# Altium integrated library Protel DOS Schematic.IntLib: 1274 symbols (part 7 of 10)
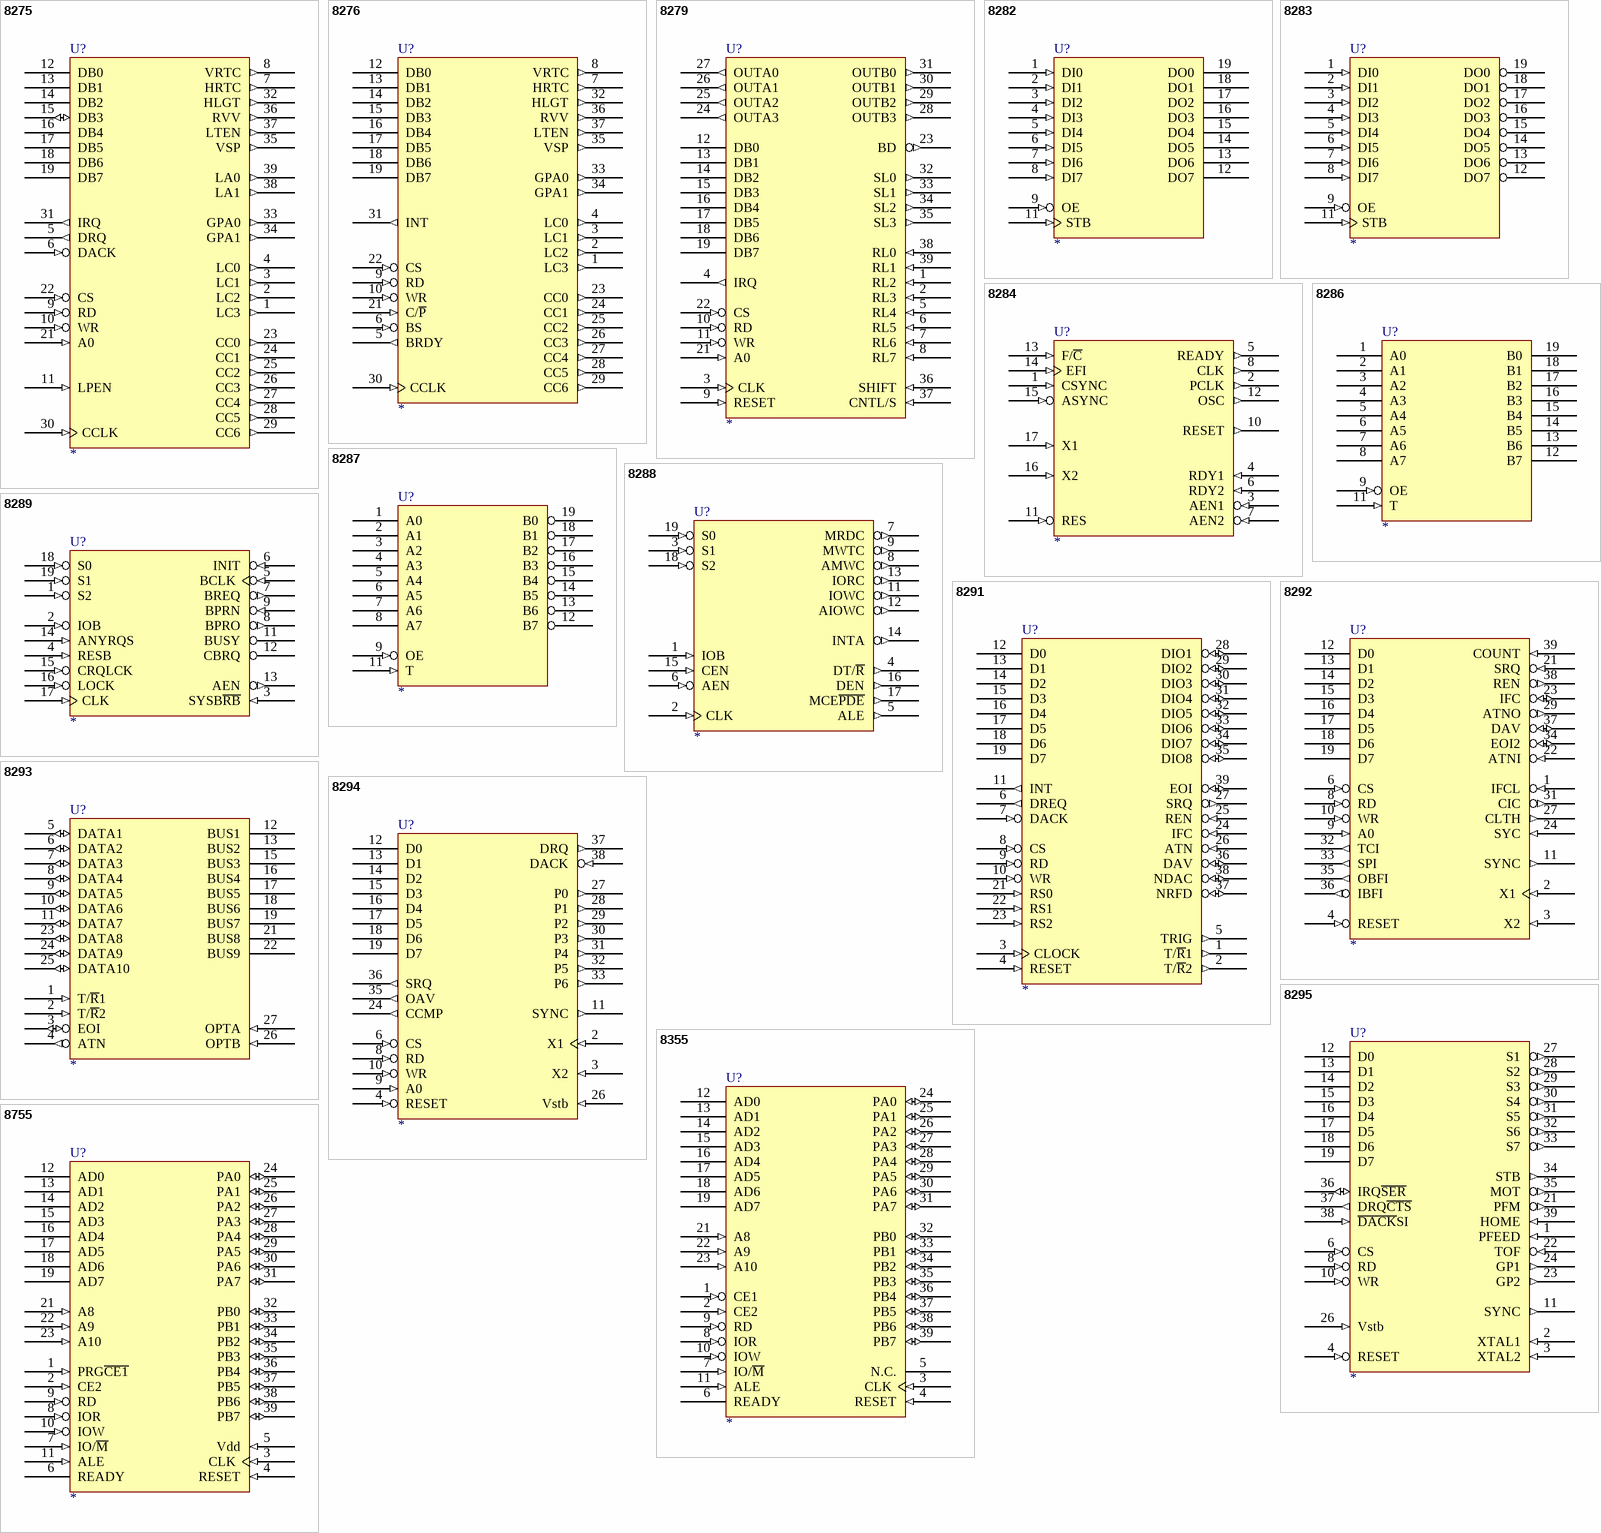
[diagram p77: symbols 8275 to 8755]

## 8293
designator U?
footprint DIP-28
pins: 1 T/~{R}1 (in), 2 T/~{R}2 (in), 3 EOI (io), 4 ATN (out), 5 DATA1 (io), 6 DATA2 (io), 7 DATA3 (io), 8 DATA4 (io), 9 DATA5 (io), 10 DATA6 (io), 11 DATA7 (io), 12 BUS1 (hiz), 13 BUS2 (hiz), 14 GND (power) hidden to GND, 15 BUS3 (hiz), 16 BUS4 (hiz), 17 BUS5 (hiz), 18 BUS6 (hiz), 19 BUS7 (hiz), 20 GND (power) hidden to GND, 21 BUS8 (hiz), 22 BUS9 (hiz), 23 DATA8 (io), 24 DATA9 (io), 25 DATA10 (io), 26 OPTB (in), 27 OPTA (in), 28 VCC (power) hidden to VCC
2 alternate drawings of the same symbol

## 8294
designator U?
footprint DIP-40
pins: 2 X1 (in), 3 X2 (in), 4 RESET (in), 5 VCC (power) hidden to VCC, 6 CS (in), 7 GND (power) hidden to GND, 8 RD (in), 9 A0 (in), 10 WR (in), 11 SYNC (out), 12 D0 (hiz), 13 D1 (hiz), 14 D2 (hiz), 15 D3 (hiz), 16 D4 (hiz), 17 D5 (hiz), 18 D6 (hiz), 19 D7 (hiz), 20 GND (power) hidden to GND, 24 CCMP (out), 25 VCC (power) hidden to VCC, 26 Vstb (in), 27 P0 (out), 28 P1 (out), 29 P2 (out), 30 P3 (out), 31 P4 (out), 32 P5 (out), 33 P6 (out), 35 OAV (out), 36 SRQ (out), 37 DRQ (out), 38 DACK (in), 40 VCC (power) hidden to VCC
2 alternate drawings of the same symbol

## 8295
designator U?
footprint DIP-40
pins: 1 PFEED (in), 2 XTAL1 (in), 3 XTAL2 (in), 4 RESET (in), 5 VCC (power) hidden to VCC, 6 CS (in), 7 GND (power) hidden to GND, 8 RD (in), 9 VCC (power) hidden to VCC, 10 WR (in), 11 SYNC (out), 12 D0 (hiz), 13 D1 (hiz), 14 D2 (hiz), 15 D3 (hiz), 16 D4 (hiz), 17 D5 (hiz), 18 D6 (hiz), 19 D7 (hiz), 20 GND (power) hidden to GND, 21 PFM (out), 22 TOF (in), 23 GP2 (out), 24 GP1 (out), 25 VCC (power) hidden to VCC, 26 Vstb (in), 27 S1 (out), 28 S2 (out), 29 S3 (out), 30 S4 (out), 31 S5 (out), 32 S6 (out), 33 S7 (out), 34 STB (out), 35 MOT (out), 36 IRQ~{SER} (io), 37 DRQ~{CTS} (out), 38 ~{DACK}SI (in), 39 HOME (in), 40 VCC (power) hidden to VCC
2 alternate drawings of the same symbol

## 8355
designator U?
footprint DIP-40
pins: 1 CE1 (in), 2 CE2 (in), 3 CLK (in), 4 RESET (in), 5 N.C., 6 READY (hiz), 7 IO/~{M} (in), 8 IOR (in), 9 RD (in), 10 IOW (in), 11 ALE (in), 12 AD0 (hiz), 13 AD1 (hiz), 14 AD2 (hiz), 15 AD3 (hiz), 16 AD4 (hiz), 17 AD5 (hiz), 18 AD6 (hiz), 19 AD7 (hiz), 20 GND (power) hidden to GND, 21 A8 (in), 22 A9 (in), 23 A10 (in), 24 PA0 (io), 25 PA1 (io), 26 PA2 (io), 27 PA3 (io), 28 PA4 (io), 29 PA5 (io), 30 PA6 (io), 31 PA7 (io), 32 PB0 (io), 33 PB1 (io), 34 PB2 (io), 35 PB3 (io), 36 PB4 (io), 37 PB5 (io), 38 PB6 (io), 39 PB7 (io), 40 VCC (power) hidden to VCC
2 alternate drawings of the same symbol

## 8755
designator U?
footprint DIP-40
pins: 1 PRG~{CE1} (in), 2 CE2 (in), 3 CLK (in), 4 RESET (in), 5 Vdd (in), 6 READY (hiz), 7 IO/~{M} (in), 8 IOR (in), 9 RD (in), 10 IOW (in), 11 ALE (in), 12 AD0 (hiz), 13 AD1 (hiz), 14 AD2 (hiz), 15 AD3 (hiz), 16 AD4 (hiz), 17 AD5 (hiz), 18 AD6 (hiz), 19 AD7 (hiz), 20 GND (power) hidden to GND, 21 A8 (in), 22 A9 (in), 23 A10 (in), 24 PA0 (io), 25 PA1 (io), 26 PA2 (io), 27 PA3 (io), 28 PA4 (io), 29 PA5 (io), 30 PA6 (io), 31 PA7 (io), 32 PB0 (io), 33 PB1 (io), 34 PB2 (io), 35 PB3 (io), 36 PB4 (io), 37 PB5 (io), 38 PB6 (io), 39 PB7 (io), 40 VCC (power) hidden to VCC
2 alternate drawings of the same symbol

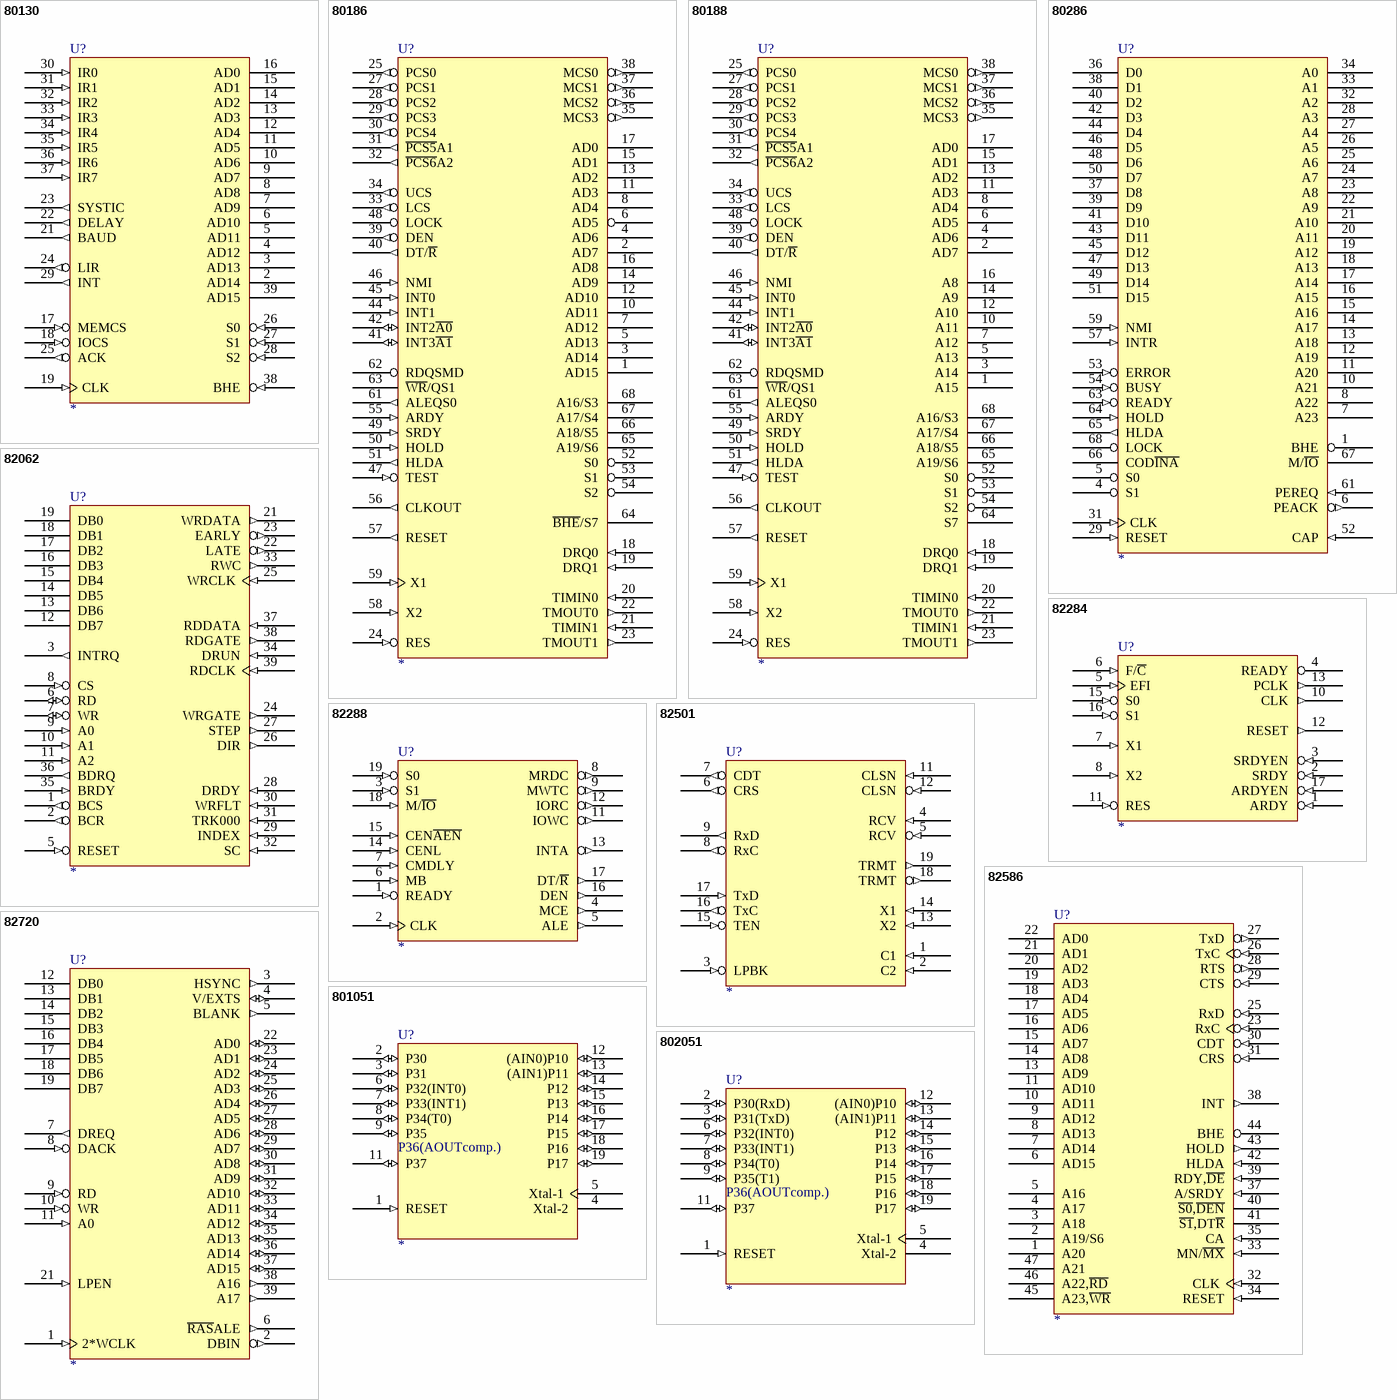
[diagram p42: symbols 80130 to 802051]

## 80130
designator U?
footprint DIP-40
pins: 1 GND (power) hidden to GND, 2 AD14 (hiz), 3 AD13 (hiz), 4 AD12 (hiz), 5 AD11 (hiz), 6 AD10 (hiz), 7 AD9 (hiz), 8 AD8 (hiz), 9 AD7 (hiz), 10 AD6 (hiz), 11 AD5 (hiz), 12 AD4 (hiz), 13 AD3 (hiz), 14 AD2 (hiz), 15 AD1 (hiz), 16 AD0 (hiz), 17 MEMCS (in), 18 IOCS (in), 19 CLK (in), 20 GND (power) hidden to GND, 21 BAUD (out), 22 DELAY (out), 23 SYSTIC (out), 24 LIR (out), 25 ACK (out), 26 S0 (in), 27 S1 (in), 28 S2 (in), 29 INT (out), 30 IR0 (in), 31 IR1 (in), 32 IR2 (in), 33 IR3 (in), 34 IR4 (in), 35 IR5 (in), 36 IR6 (in), 37 IR7 (in), 38 BHE (in), 39 AD15 (hiz), 40 VCC (power) hidden to VCC
2 alternate drawings of the same symbol

## 80186
designator U?
footprint JEDECA-68
pins: 1 AD15 (hiz), 2 AD7 (hiz), 3 AD14 (hiz), 4 AD6 (hiz), 5 AD13 (hiz), 6 AD5 (hiz), 7 AD12 (hiz), 8 AD4 (hiz), 9 VCC (power) hidden to VCC, 10 AD11 (hiz), 11 AD3 (hiz), 12 AD10 (hiz), 13 AD2 (hiz), 14 AD9 (hiz), 15 AD1 (hiz), 16 AD8 (hiz), 17 AD0 (hiz), 18 DRQ0 (in), 19 DRQ1 (in), 20 TIMIN0 (in), 21 TIMIN1 (in), 22 TMOUT0 (out), 23 TMOUT1 (out), 24 RES (in), 25 PCS0 (out), 26 GND (power) hidden to GND, 27 PCS1 (out), 28 PCS2 (out), 29 PCS3 (out), 30 PCS4 (out), 31 ~{PCS5}A1 (out), 32 ~{PCS6}A2 (out), 33 LCS (out), 34 UCS (out), 35 MCS3 (out), 36 MCS2 (out), 37 MCS1 (out), 38 MCS0 (out), 39 DEN (out), 40 DT/~{R} (out), 41 INT3~{A1} (io), 42 INT2~{A0} (io), 43 VCC (power) hidden to VCC, 44 INT1 (in), 45 INT0 (in), 46 NMI (in), 47 TEST (in), 48 LOCK (hiz), 49 SRDY (in), 50 HOLD (in), 51 HLDA (out), 52 S0 (hiz), 53 S1 (hiz), 54 S2 (hiz), 55 ARDY (in), 56 CLKOUT (out), 57 RESET (out), 58 X2 (in), 59 X1 (in), 60 GND (power) hidden to GND, 61 ALEQS0 (out), 62 RDQSMD (hiz), 63 ~{WR}/QS1 (hiz), 64 ~{BHE}/S7 (hiz), 65 A19/S6 (hiz), 66 A18/S5 (hiz), 67 A17/S4 (hiz), 68 A16/S3 (hiz)
2 alternate drawings of the same symbol

## 80188
designator U?
footprint JEDECA-68
pins: 1 A15 (hiz), 2 AD7 (hiz), 3 A14 (hiz), 4 AD6 (hiz), 5 A13 (hiz), 6 AD5 (hiz), 7 A12 (hiz), 8 AD4 (hiz), 9 VCC (power) hidden to VCC, 10 A11 (hiz), 11 AD3 (hiz), 12 A10 (hiz), 13 AD2 (hiz), 14 A9 (hiz), 15 AD1 (hiz), 16 A8 (hiz), 17 AD0 (hiz), 18 DRQ0 (in), 19 DRQ1 (in), 20 TIMIN0 (in), 21 TIMIN1 (in), 22 TMOUT0 (out), 23 TMOUT1 (out), 24 RES (in), 25 PCS0 (out), 26 GND (power) hidden to GND, 27 PCS1 (out), 28 PCS2 (out), 29 PCS3 (out), 30 PCS4 (out), 31 ~{PCS5}A1 (out), 32 ~{PCS6}A2 (out), 33 LCS (out), 34 UCS (out), 35 MCS3 (out), 36 MCS2 (out), 37 MCS1 (out), 38 MCS0 (out), 39 DEN (out), 40 DT/~{R} (out), 41 INT3~{A1} (io), 42 INT2~{A0} (io), 43 VCC (power) hidden to VCC, 44 INT1 (in), 45 INT0 (in), 46 NMI (in), 47 TEST (in), 48 LOCK (hiz), 49 SRDY (in), 50 HOLD (in), 51 HLDA (out), 52 S0 (hiz), 53 S1 (hiz), 54 S2 (hiz), 55 ARDY (in), 56 CLKOUT (out), 57 RESET (out), 58 X2 (in), 59 X1 (in), 60 GND (power) hidden to GND, 61 ALEQS0 (out), 62 RDQSMD (hiz), 63 ~{WR}/QS1 (hiz), 64 S7 (hiz), 65 A19/S6 (hiz), 66 A18/S5 (hiz), 67 A17/S4 (hiz), 68 A16/S3 (hiz)
2 alternate drawings of the same symbol

## 80286
designator U?
footprint JEDECA-68
pins: 1 BHE (hiz), 4 S1 (hiz), 5 S0 (hiz), 6 PEACK (out), 7 A23 (hiz), 8 A22 (hiz), 9 GND (power) hidden to GND, 10 A21 (hiz), 11 A20 (hiz), 12 A19 (hiz), 13 A18 (hiz), 14 A17 (hiz), 15 A16 (hiz), 16 A15 (hiz), 17 A14 (hiz), 18 A13 (hiz), 19 A12 (hiz), 20 A11 (hiz), 21 A10 (hiz), 22 A9 (hiz), 23 A8 (hiz), 24 A7 (hiz), 25 A6 (hiz), 26 A5 (hiz), 27 A4 (hiz), 28 A3 (hiz), 29 RESET (in), 30 VCC (power) hidden to VCC, 31 CLK (in), 32 A2 (hiz), 33 A1 (hiz), 34 A0 (hiz), 35 GND (power) hidden to GND, 36 D0 (hiz), 37 D8 (hiz), 38 D1 (hiz), 39 D9 (hiz), 40 D2 (hiz), 41 D10 (hiz), 42 D3 (hiz), 43 D11 (hiz), 44 D4 (hiz), 45 D12 (hiz), 46 D5 (hiz), 47 D13 (hiz), 48 D6 (hiz), 49 D14 (hiz), 50 D7 (hiz), 51 D15 (hiz), 52 CAP (in), 53 ERROR (in), 54 BUSY (in), 57 INTR (in), 59 NMI (in), 60 GND (power) hidden to GND, 61 PEREQ (in), 62 VCC (power) hidden to VCC, 63 READY (in), 64 HOLD (in), 65 HLDA (out), 66 COD~{INA} (hiz), 67 M/~{IO} (hiz), 68 LOCK (hiz)
2 alternate drawings of the same symbol

## 82062
designator U?
footprint DIP-40
pins: 1 BCS (out), 2 BCR (out), 3 INTRQ (out), 5 RESET (in), 6 RD (io), 7 WR (io), 8 CS (in), 9 A0 (in), 10 A1 (in), 11 A2 (in), 12 DB7 (hiz), 13 DB6 (hiz), 14 DB5 (hiz), 15 DB4 (hiz), 16 DB3 (hiz), 17 DB2 (hiz), 18 DB1 (hiz), 19 DB0 (hiz), 20 GND (power) hidden to GND, 21 WRDATA (out), 22 LATE (out), 23 EARLY (out), 24 WRGATE (out), 25 WRCLK (in), 26 DIR (out), 27 STEP (out), 28 DRDY (in), 29 INDEX (in), 30 WRFLT (in), 31 TRK000 (in), 32 SC (in), 33 RWC (out), 34 DRUN (in), 35 BRDY (in), 36 BDRQ (out), 37 RDDATA (in), 38 RDGATE (out), 39 RDCLK (in), 40 VCC (power) hidden to VCC
2 alternate drawings of the same symbol

## 82284
designator U?
footprint DIP-18
pins: 1 ARDY (in), 2 SRDY (in), 3 SRDYEN (in), 4 READY (oc), 5 EFI (in), 6 F/~{C} (in), 7 X1 (in), 8 X2 (in), 9 GND (power) hidden to GND, 10 CLK (out), 11 RES (in), 12 RESET (out), 13 PCLK (out), 15 S0 (in), 16 S1 (in), 17 ARDYEN (in), 18 VCC (power) hidden to VCC
2 alternate drawings of the same symbol

## 82288
designator U?
footprint DIP-20
pins: 1 READY (in), 2 CLK (in), 3 S1 (in), 4 MCE (out), 5 ALE (out), 6 MB (in), 7 CMDLY (in), 8 MRDC (out), 9 MWTC (out), 10 GND (power) hidden to GND, 11 IOWC (out), 12 IORC (out), 13 INTA (out), 14 CENL (in), 15 CEN~{AEN} (in), 16 DEN (out), 17 DT/~{R} (out), 18 M/~{IO} (in), 19 S0 (in), 20 VCC (power) hidden to VCC
2 alternate drawings of the same symbol

## 82501
designator U?
footprint DIP-20
pins: 1 C1 (in), 2 C2 (in), 3 LPBK (in), 4 RCV (in), 5 RCV (in), 6 CRS (out), 7 CDT (out), 8 RxC (out), 9 RxD (out), 10 GND (power) hidden to GND, 11 CLSN (in), 12 CLSN (in), 13 X2 (in), 14 X1 (in), 15 TEN (in), 16 TxC (out), 17 TxD (in), 18 TRMT (out), 19 TRMT (out), 20 VCC (power) hidden to VCC
2 alternate drawings of the same symbol

## 82586
designator U?
footprint DIP-48
pins: 1 A20 (hiz), 2 A19/S6 (hiz), 3 A18 (hiz), 4 A17 (hiz), 5 A16 (hiz), 6 AD15 (hiz), 7 AD14 (hiz), 8 AD13 (hiz), 9 AD12 (hiz), 10 AD11 (hiz), 11 AD10 (hiz), 12 GND (power) hidden to GND, 13 AD9 (hiz), 14 AD8 (hiz), 15 AD7 (hiz), 16 AD6 (hiz), 17 AD5 (hiz), 18 AD4 (hiz), 19 AD3 (hiz), 20 AD2 (hiz), 21 AD1 (hiz), 22 AD0 (hiz), 23 RxC (in), 24 GND (power) hidden to GND, 25 RxD (in), 26 TxC (in), 27 TxD (out), 28 RTS (out), 29 CTS (in), 30 CDT (in), 31 CRS (in), 32 CLK (in), 33 MN/~{MX} (in), 34 RESET (in), 35 CA (in), 36 VCC (power) hidden to VCC, 37 A/SRDY (in), 38 INT (out), 39 RDY,~{DE} (in), 40 ~{S0},~{DEN} (hiz), 41 ~{S1},DT~{R} (hiz), 42 HLDA (in), 43 HOLD (out), 44 BHE (hiz), 45 A23,~{WR} (hiz), 46 A22,~{RD} (hiz), 47 A21 (hiz), 48 VCC (power) hidden to VCC
2 alternate drawings of the same symbol

## 82720
designator U?
footprint DIP-40
pins: 1 2*WCLK (in), 2 VCC (power) hidden to VCC, 2 DBIN (out), 3 HSYNC (out), 4 V/EXTS (io), 5 BLANK (out), 6 ~{RAS}ALE (out), 7 DREQ (out), 8 DACK (in), 9 RD (in), 10 WR (in), 11 A0 (in), 12 DB0 (hiz), 13 DB1 (hiz), 14 DB2 (hiz), 15 DB3 (hiz), 16 DB4 (hiz), 17 DB5 (hiz), 18 DB6 (hiz), 19 DB7 (hiz), 20 GND (power) hidden to GND, 21 LPEN (in), 22 AD0 (io), 23 AD1 (io), 24 AD2 (io), 25 AD3 (io), 26 AD4 (io), 27 AD5 (io), 28 AD6 (io), 29 AD7 (io), 30 AD8 (io), 31 AD9 (io), 32 AD10 (io), 33 AD11 (io), 34 AD12 (io), 35 AD13 (io), 36 AD14 (io), 37 AD15 (io), 38 A16 (out), 39 A17 (out)
2 alternate drawings of the same symbol

## 801051
designator U?
footprint DIP20E
pins: 1 RESET (in), 2 P30 (io), 3 P31 (io), 4 Xtal-2, 5 Xtal-1, 6 P32(INT0) (io), 7 P33(INT1) (io), 8 P34(T0) (io), 9 P35 (io), 10 GND (power) hidden to GND, 11 P37 (io), 12 (AIN0)P10 (io), 13 (AIN1)P11 (io), 14 P12 (io), 15 P13 (io), 16 P14 (io), 17 P15 (io), 18 P16 (io), 19 P17 (io), 20 VCC (power) hidden to VCC
2 alternate drawings of the same symbol

## 802051
designator U?
footprint DIP20E
pins: 1 RESET (in), 2 P30(RxD) (io), 3 P31(TxD) (io), 4 Xtal-2, 5 Xtal-1, 6 P32(INT0) (io), 7 P33(INT1) (io), 8 P34(T0) (io), 9 P35(T1) (io), 10 GND (power) hidden to GND, 11 P37 (io), 12 (AIN0)P10 (io), 13 (AIN1)P11 (io), 14 P12 (io), 15 P13 (io), 16 P14 (io), 17 P15 (io), 18 P16 (io), 19 P17 (io), 20 VCC (power) hidden to VCC
2 alternate drawings of the same symbol


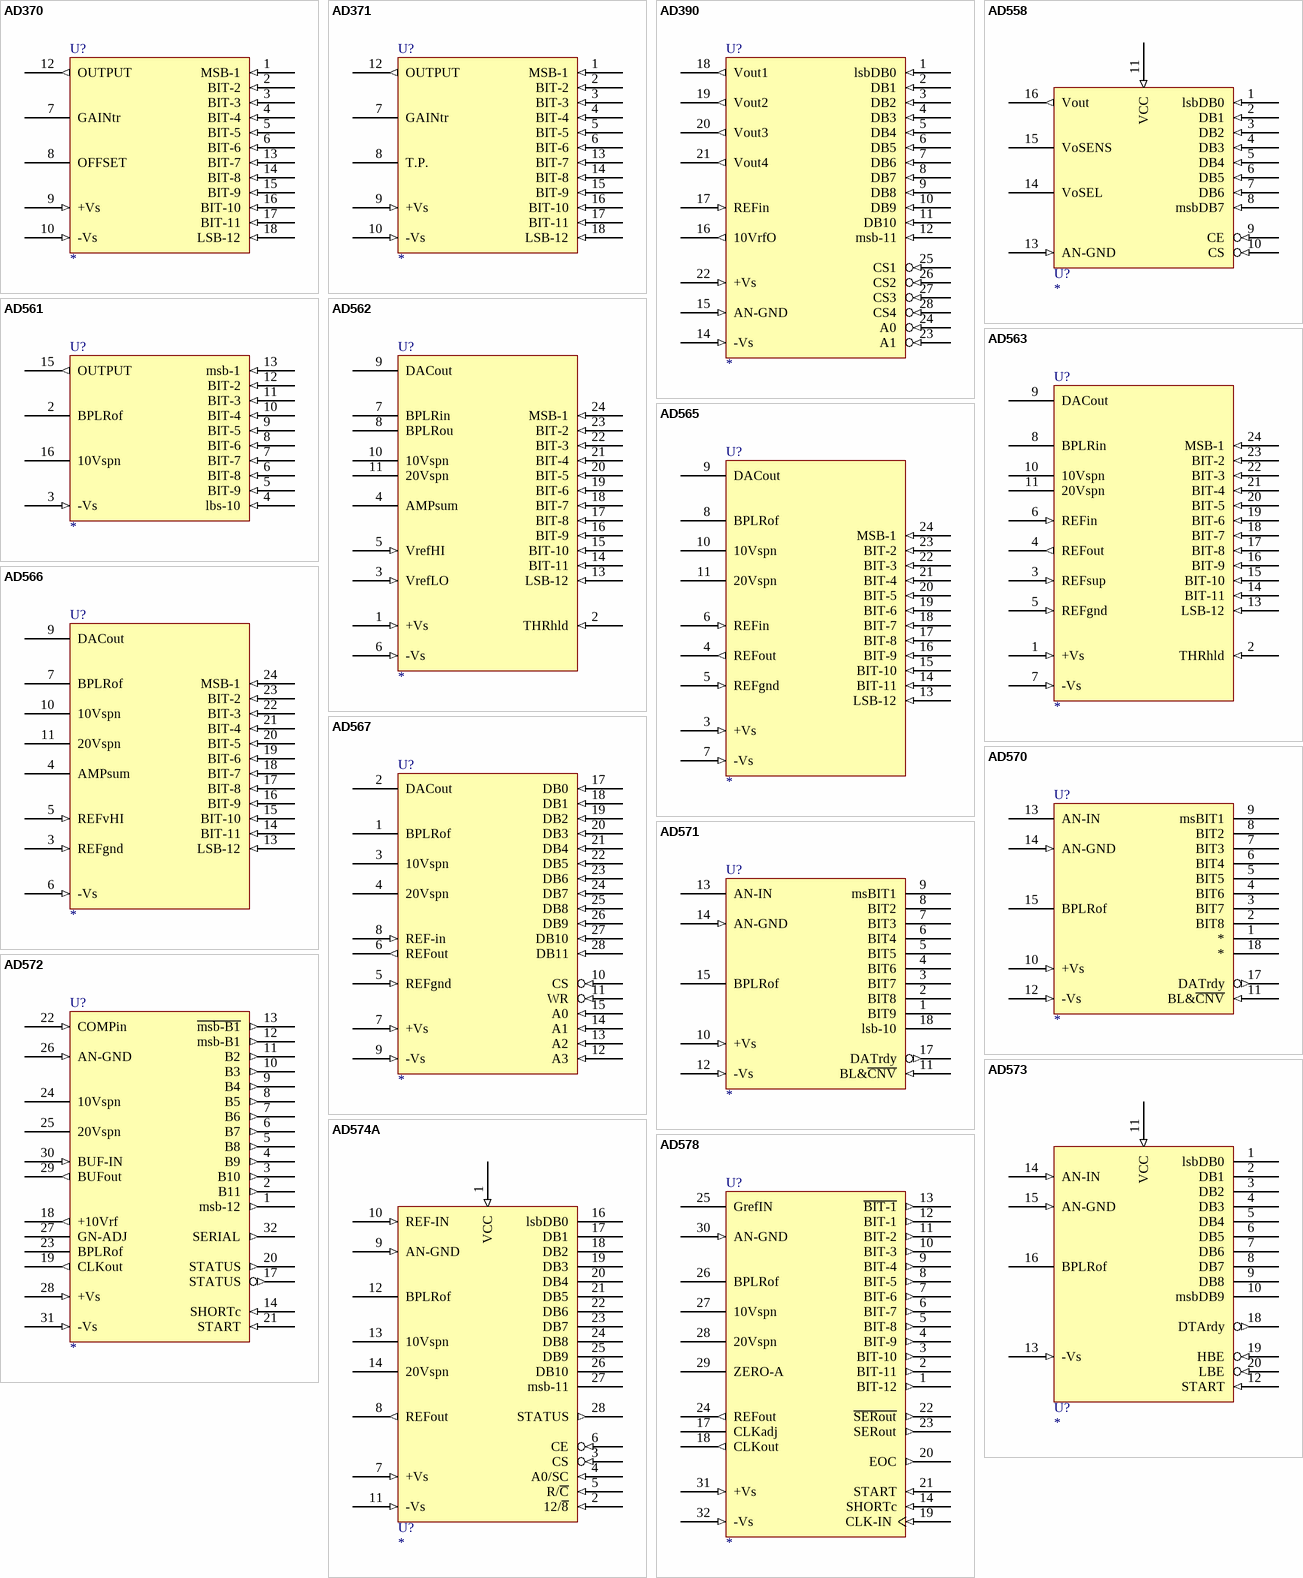
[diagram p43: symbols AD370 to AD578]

## AD370
designator U?
footprint DIP-18
pins: 1 MSB-1 (in), 2 BIT-2 (in), 3 BIT-3 (in), 4 BIT-4 (in), 5 BIT-5 (in), 6 BIT-6 (in), 7 GAINtr, 8 OFFSET, 9 +Vs (in), 10 -Vs (in), 11 GND (power) hidden to GND, 12 OUTPUT (out), 13 BIT-7 (in), 14 BIT-8 (in), 15 BIT-9 (in), 16 BIT-10 (in), 17 BIT-11 (in), 18 LSB-12 (in)
2 alternate drawings of the same symbol

## AD371
designator U?
footprint DIP-18
pins: 1 MSB-1 (in), 2 BIT-2 (in), 3 BIT-3 (in), 4 BIT-4 (in), 5 BIT-5 (in), 6 BIT-6 (in), 7 GAINtr, 8 T.P., 9 +Vs (in), 10 -Vs (in), 11 GND (power) hidden to GND, 12 OUTPUT (out), 13 BIT-7 (in), 14 BIT-8 (in), 15 BIT-9 (in), 16 BIT-10 (in), 17 BIT-11 (in), 18 LSB-12 (in)
2 alternate drawings of the same symbol

## AD390
designator U?
footprint HY28
pins: 1 lsbDB0 (in), 2 DB1 (in), 3 DB2 (in), 4 DB3 (in), 5 DB4 (in), 6 DB5 (in), 7 DB6 (in), 8 DB7 (in), 9 DB8 (in), 10 DB9 (in), 11 DB10 (in), 12 msb-11 (in), 13 GND (power) hidden to GND, 14 -Vs (in), 15 AN-GND (in), 16 10VrfO (out), 17 REFin (in), 18 Vout1 (out), 19 Vout2 (out), 20 Vout3 (out), 21 Vout4 (out), 22 +Vs (in), 23 A1 (in), 24 A0 (in), 25 CS1 (in), 26 CS2 (in), 27 CS3 (in), 28 CS4 (in)
2 alternate drawings of the same symbol

## AD558
designator U?
footprint DIP-16
pins: 1 lsbDB0 (in), 2 DB1 (in), 3 DB2 (in), 4 DB3 (in), 5 DB4 (in), 6 DB5 (in), 7 DB6 (in), 8 msbDB7 (in), 9 CE (in), 10 CS (in), 11 VCC (in), 12 GND (power) hidden to GND, 13 AN-GND (in), 14 VoSEL, 15 VoSENS, 16 Vout (out)
2 alternate drawings of the same symbol

## AD561
designator U?
footprint DIP-16
pins: 1 GND (power) hidden to GND, 2 BPLRof, 3 -Vs (in), 4 lbs-10 (in), 5 BIT-9 (in), 6 BIT-8 (in), 7 BIT-7 (in), 8 BIT-6 (in), 9 BIT-5 (in), 10 BIT-4 (in), 11 BIT-3 (in), 12 BIT-2 (in), 13 msb-1 (in), 14 VCC (power) hidden to VCC, 15 OUTPUT (out), 16 10Vspn
2 alternate drawings of the same symbol

## AD562
designator U?
footprint DIP-24
pins: 1 +Vs (in), 2 THRhld (in), 3 VrefLO (in), 4 AMPsum, 5 VrefHI (in), 6 -Vs (in), 7 BPLRin, 8 BPLRou, 9 DACout, 10 10Vspn, 11 20Vspn, 12 GND (power) hidden to GND, 13 LSB-12 (in), 14 BIT-11 (in), 15 BIT-10 (in), 16 BIT-9 (in), 17 BIT-8 (in), 18 BIT-7 (in), 19 BIT-6 (in), 20 BIT-5 (in), 21 BIT-4 (in), 22 BIT-3 (in), 23 BIT-2 (in), 24 MSB-1 (in)
2 alternate drawings of the same symbol

## AD563
designator U?
footprint DIP-24
pins: 1 +Vs (in), 2 THRhld (in), 3 REFsup (in), 4 REFout (out), 5 REFgnd (in), 6 REFin (in), 7 -Vs (in), 8 BPLRin, 9 DACout, 10 10Vspn, 11 20Vspn, 12 GND (power) hidden to GND, 13 LSB-12 (in), 14 BIT-11 (in), 15 BIT-10 (in), 16 BIT-9 (in), 17 BIT-8 (in), 18 BIT-7 (in), 19 BIT-6 (in), 20 BIT-5 (in), 21 BIT-4 (in), 22 BIT-3 (in), 23 BIT-2 (in), 24 MSB-1 (in)
2 alternate drawings of the same symbol

## AD565
designator U?
footprint DIP-24
pins: 3 +Vs (in), 4 REFout (out), 5 REFgnd (in), 6 REFin (in), 7 -Vs (in), 8 BPLRof, 9 DACout, 10 10Vspn, 11 20Vspn, 12 GND (power) hidden to GND, 13 LSB-12 (in), 14 BIT-11 (in), 15 BIT-10 (in), 16 BIT-9 (in), 17 BIT-8 (in), 18 BIT-7 (in), 19 BIT-6 (in), 20 BIT-5 (in), 21 BIT-4 (in), 22 BIT-3 (in), 23 BIT-2 (in), 24 MSB-1 (in)
2 alternate drawings of the same symbol

## AD566
designator U?
footprint DIP-24
pins: 3 REFgnd (in), 4 AMPsum, 5 REFvHI (in), 6 -Vs (in), 7 BPLRof, 9 DACout, 10 10Vspn, 11 20Vspn, 12 GND (power) hidden to GND, 13 LSB-12 (in), 14 BIT-11 (in), 15 BIT-10 (in), 16 BIT-9 (in), 17 BIT-8 (in), 18 BIT-7 (in), 19 BIT-6 (in), 20 BIT-5 (in), 21 BIT-4 (in), 22 BIT-3 (in), 23 BIT-2 (in), 24 MSB-1 (in)
2 alternate drawings of the same symbol

## AD567
designator U?
footprint DIP-28
pins: 1 BPLRof, 2 DACout, 3 10Vspn, 4 20Vspn, 5 REFgnd (in), 6 REFout (out), 7 +Vs (in), 8 REF-in (in), 9 -Vs (in), 10 CS (in), 11 WR (in), 12 A3 (in), 13 A2 (in), 14 A1 (in), 15 A0 (in), 16 GND (power) hidden to GND, 17 DB0 (in), 18 DB1 (in), 19 DB2 (in), 20 DB3 (in), 21 DB4 (in), 22 DB5 (in), 23 DB6 (in), 24 DB7 (in), 25 DB8 (in), 26 DB9 (in), 27 DB10 (in), 28 DB11 (in)
2 alternate drawings of the same symbol

## AD570
designator U?
footprint DIP-18
pins: 1 * (hiz), 2 BIT8 (hiz), 3 BIT7 (hiz), 4 BIT6 (hiz), 5 BIT5 (hiz), 6 BIT4 (hiz), 7 BIT3 (hiz), 8 BIT2 (hiz), 9 msBIT1 (hiz), 10 +Vs (in), 11 BL&~{CNV} (in), 12 -Vs (in), 13 AN-IN, 14 AN-GND (in), 15 BPLRof, 16 GND (power) hidden to GND, 17 DATrdy (out), 18 * (hiz)
2 alternate drawings of the same symbol

## AD571
designator U?
footprint DIP-18
pins: 1 BIT9 (hiz), 2 BIT8 (hiz), 3 BIT7 (hiz), 4 BIT6 (hiz), 5 BIT5 (hiz), 6 BIT4 (hiz), 7 BIT3 (hiz), 8 BIT2 (hiz), 9 msBIT1 (hiz), 10 +Vs (in), 11 BL&~{CNV} (in), 12 -Vs (in), 13 AN-IN, 14 AN-GND (in), 15 BPLRof, 16 GND (power) hidden to GND, 17 DATrdy (out), 18 lsb-10 (hiz)
2 alternate drawings of the same symbol

## AD572
designator U?
footprint DIP-32
pins: 1 msb-12 (out), 2 B11 (out), 3 B10 (out), 4 B9 (out), 5 B8 (out), 6 B7 (out), 7 B6 (out), 8 B5 (out), 9 B4 (out), 10 B3 (out), 11 B2 (out), 12 msb-B1 (out), 13 ~{msb-B1} (out), 14 SHORTc (in), 15 GND (power) hidden to GND, 16 VCC (power) hidden to VCC, 17 STATUS (out), 18 +10Vrf (out), 19 CLKout (out), 20 STATUS (out), 21 START (in), 22 COMPin (in), 23 BPLRof, 24 10Vspn, 25 20Vspn, 26 AN-GND (in), 27 GN-ADJ, 28 +Vs (in), 29 BUFout (out), 30 BUF-IN (in), 31 -Vs (in), 32 SERIAL (out)
2 alternate drawings of the same symbol

## AD573
designator U?
footprint DIP-20
pins: 1 lsbDB0 (hiz), 2 DB1 (hiz), 3 DB2 (hiz), 4 DB3 (hiz), 5 DB4 (hiz), 6 DB5 (hiz), 7 DB6 (hiz), 8 DB7 (hiz), 9 DB8 (hiz), 10 msbDB9 (hiz), 11 VCC (in), 12 START (in), 13 -Vs (in), 14 AN-IN (in), 15 AN-GND (in), 16 BPLRof, 17 GND (power) hidden to GND, 18 DTArdy (out), 19 HBE (in), 20 LBE (in)
2 alternate drawings of the same symbol

## AD574A
designator U?
footprint DIP-28
pins: 1 VCC (in), 2 12/~{8} (in), 3 CS (in), 4 A0/SC (in), 5 R/~{C} (in), 6 CE (in), 7 +Vs (in), 8 REFout (out), 9 AN-GND (in), 10 REF-IN (in), 11 -Vs (in), 12 BPLRof, 13 10Vspn, 14 20Vspn, 15 GND (power) hidden to GND, 16 lsbDB0 (hiz), 17 DB1 (hiz), 18 DB2 (hiz), 19 DB3 (hiz), 20 DB4 (hiz), 21 DB5 (hiz), 22 DB6 (hiz), 23 DB7 (hiz), 24 DB8 (hiz), 25 DB9 (hiz), 26 DB10 (hiz), 27 msb-11 (hiz), 28 STATUS (out)
2 alternate drawings of the same symbol

## AD578
designator U?
footprint DIP-32
pins: 1 BIT-12 (out), 2 BIT-11 (out), 3 BIT-10 (out), 4 BIT-9 (out), 5 BIT-8 (out), 6 BIT-7 (out), 7 BIT-6 (out), 8 BIT-5 (out), 9 BIT-4 (out), 10 BIT-3 (out), 11 BIT-2 (out), 12 BIT-1 (out), 13 ~{BIT-1} (out), 14 SHORTc (in), 15 GND (power) hidden to GND, 16 VCC (power) hidden to VCC, 17 CLKadj, 18 CLKout (out), 19 CLK-IN (in), 20 EOC (out), 21 START (in), 22 ~{SERout} (out), 23 SERout (out), 24 REFout (out), 25 GrefIN, 26 BPLRof, 27 10Vspn, 28 20Vspn, 29 ZERO-A, 30 AN-GND (in), 31 +Vs (in), 32 -Vs (in)
2 alternate drawings of the same symbol

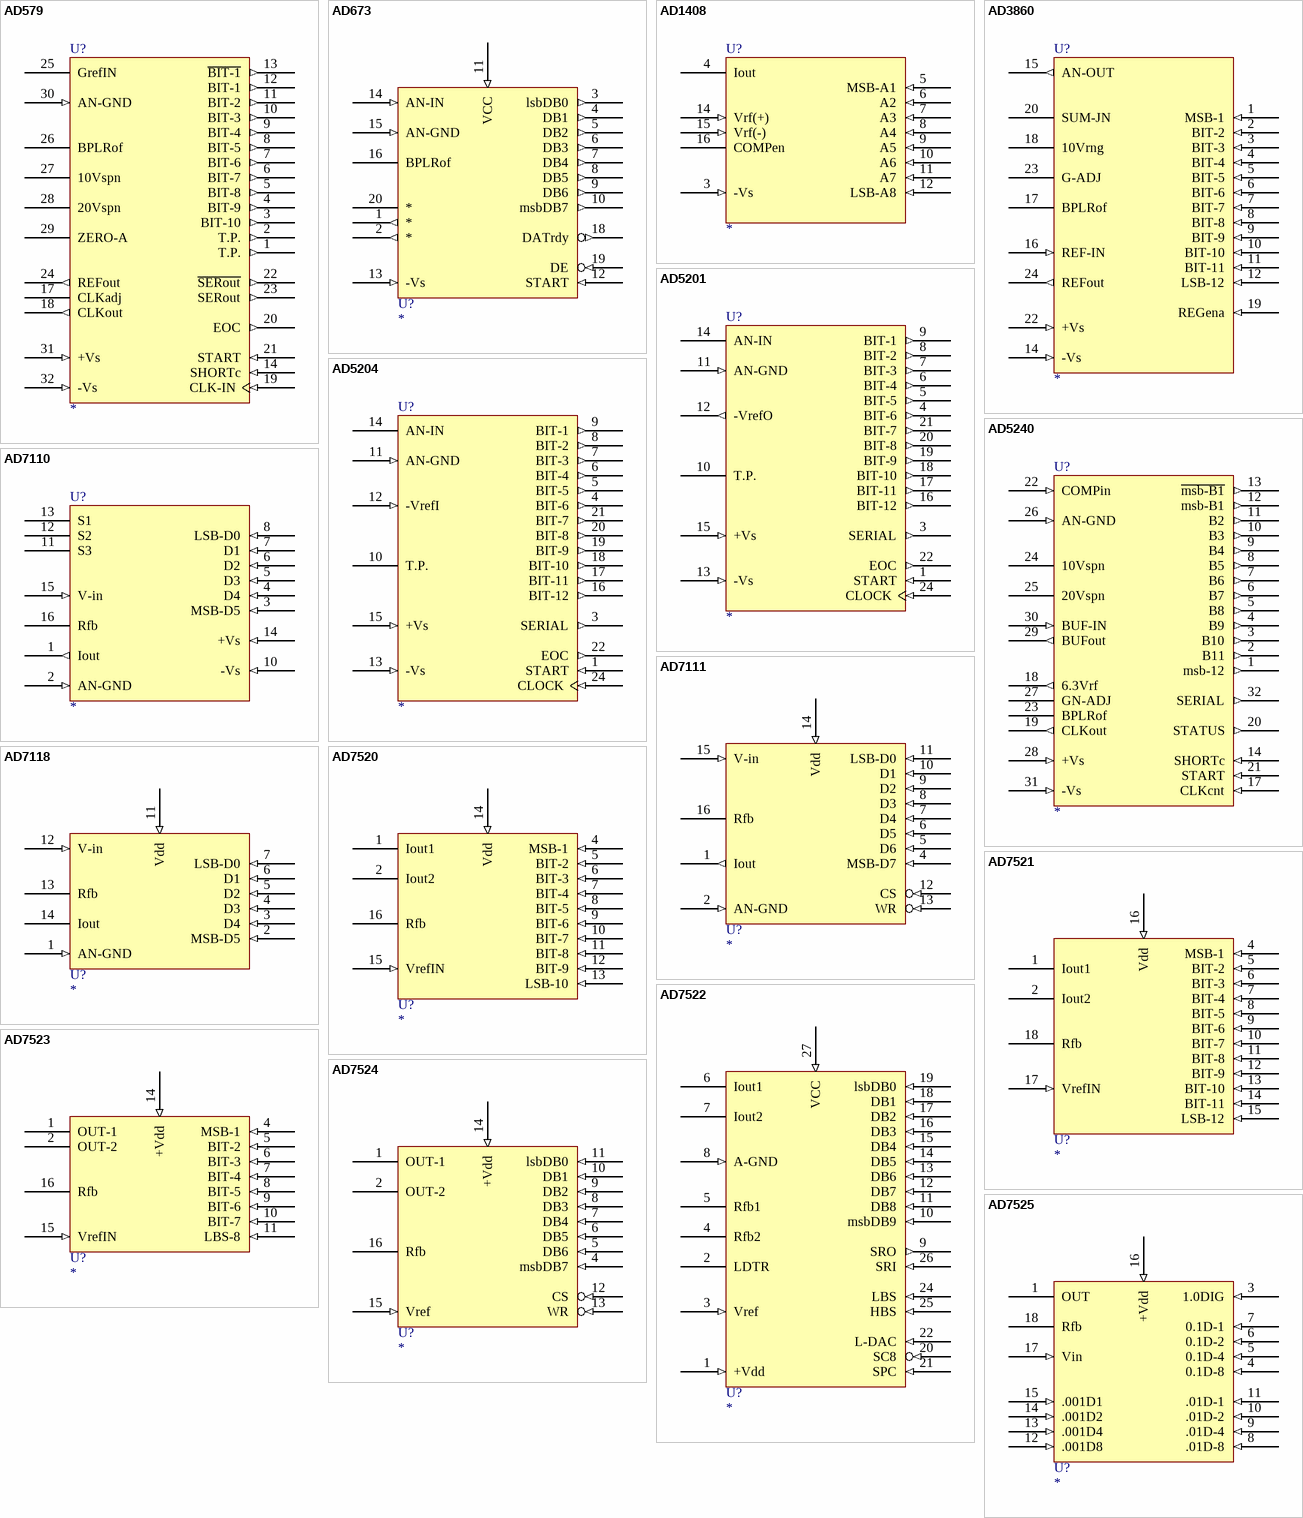
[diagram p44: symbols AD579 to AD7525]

## AD579
designator U?
footprint DIP-32
pins: 1 T.P. (out), 2 T.P. (out), 3 BIT-10 (out), 4 BIT-9 (out), 5 BIT-8 (out), 6 BIT-7 (out), 7 BIT-6 (out), 8 BIT-5 (out), 9 BIT-4 (out), 10 BIT-3 (out), 11 BIT-2 (out), 12 BIT-1 (out), 13 ~{BIT-1} (out), 14 SHORTc (in), 15 GND (power) hidden to GND, 16 VCC (power) hidden to VCC, 17 CLKadj, 18 CLKout (out), 19 CLK-IN (in), 20 EOC (out), 21 START (in), 22 ~{SERout} (out), 23 SERout (out), 24 REFout (out), 25 GrefIN, 26 BPLRof, 27 10Vspn, 28 20Vspn, 29 ZERO-A, 30 AN-GND (in), 31 +Vs (in), 32 -Vs (in)
2 alternate drawings of the same symbol

## AD673
designator U?
footprint DIP-20
pins: 1 * (out), 2 * (out), 3 lsbDB0 (out), 4 DB1 (out), 5 DB2 (out), 6 DB3 (out), 7 DB4 (out), 8 DB5 (out), 9 DB6 (out), 10 msbDB7 (out), 11 VCC (in), 12 START (in), 13 -Vs (in), 14 AN-IN (in), 15 AN-GND (in), 16 BPLRof, 17 GND (power) hidden to GND, 18 DATrdy (out), 19 DE (in), 20 *
2 alternate drawings of the same symbol

## AD1408
designator U?
footprint DIP-16
pins: 2 GND (power) hidden to GND, 3 -Vs (in), 4 Iout, 5 MSB-A1 (in), 6 A2 (in), 7 A3 (in), 8 A4 (in), 9 A5 (in), 10 A6 (in), 11 A7 (in), 12 LSB-A8 (in), 13 VCC (power) hidden to VCC, 14 Vrf(+) (in), 15 Vrf(-) (in), 16 COMPen
2 alternate drawings of the same symbol

## AD3860
designator U?
footprint DIP-24
pins: 1 MSB-1 (in), 2 BIT-2 (in), 3 BIT-3 (in), 4 BIT-4 (in), 5 BIT-5 (in), 6 BIT-6 (in), 7 BIT-7 (in), 8 BIT-8 (in), 9 BIT-9 (in), 10 BIT-10 (in), 11 BIT-11 (in), 12 LSB-12 (in), 13 VCC (power) hidden to VCC, 14 -Vs (in), 15 AN-OUT (out), 16 REF-IN (in), 17 BPLRof, 18 10Vrng, 19 REGena (in), 20 SUM-JN, 21 GND (power) hidden to GND, 22 +Vs (in), 23 G-ADJ, 24 REFout (out)
2 alternate drawings of the same symbol

## AD5201
designator U?
footprint DIP-24
pins: 1 START (in), 2 VCC (power) hidden to VCC, 3 SERIAL (out), 4 BIT-6 (out), 5 BIT-5 (out), 6 BIT-4 (out), 7 BIT-3 (out), 8 BIT-2 (out), 9 BIT-1 (out), 10 T.P., 11 AN-GND (in), 12 -VrefO (out), 13 -Vs (in), 14 AN-IN, 15 +Vs (in), 16 BIT-12 (out), 17 BIT-11 (out), 18 BIT-10 (out), 19 BIT-9 (out), 20 BIT-8 (out), 21 BIT-7 (out), 22 EOC (out), 23 GND (power) hidden to GND, 24 CLOCK (in)
2 alternate drawings of the same symbol

## AD5204
designator U?
footprint DIP-24
pins: 1 START (in), 2 VCC (power) hidden to VCC, 3 SERIAL (out), 4 BIT-6 (out), 5 BIT-5 (out), 6 BIT-4 (out), 7 BIT-3 (out), 8 BIT-2 (out), 9 BIT-1 (out), 10 T.P., 11 AN-GND (in), 12 -VrefI (in), 13 -Vs (in), 14 AN-IN, 15 +Vs (in), 16 BIT-12 (out), 17 BIT-11 (out), 18 BIT-10 (out), 19 BIT-9 (out), 20 BIT-8 (out), 21 BIT-7 (out), 22 EOC (out), 23 GND (power) hidden to GND, 24 CLOCK (in)
2 alternate drawings of the same symbol

## AD5240
designator U?
footprint DIP-32
pins: 1 msb-12 (out), 2 B11 (out), 3 B10 (out), 4 B9 (out), 5 B8 (out), 6 B7 (out), 7 B6 (out), 8 B5 (out), 9 B4 (out), 10 B3 (out), 11 B2 (out), 12 msb-B1 (out), 13 ~{msb-B1} (out), 14 SHORTc (in), 15 GND (power) hidden to GND, 16 VCC (power) hidden to VCC, 17 CLKcnt (in), 18 6.3Vrf (out), 19 CLKout (out), 20 STATUS (out), 21 START (in), 22 COMPin (in), 23 BPLRof, 24 10Vspn, 25 20Vspn, 26 AN-GND (in), 27 GN-ADJ, 28 +Vs (in), 29 BUFout (out), 30 BUF-IN (in), 31 -Vs (in), 32 SERIAL (out)
2 alternate drawings of the same symbol

## AD7110
designator U?
footprint DIP-16
pins: 1 Iout (out), 2 AN-GND (in), 3 MSB-D5 (in), 4 D4 (in), 5 D3 (in), 6 D2 (in), 7 D1 (in), 8 LSB-D0 (in), 9 GND (power) hidden to GND, 10 -Vs (in), 11 S3, 12 S2, 13 S1, 14 +Vs (in), 15 V-in (in), 16 Rfb
2 alternate drawings of the same symbol

## AD7111
designator U?
footprint DIP-16
pins: 1 Iout (out), 2 AN-GND (in), 3 GND (power) hidden to GND, 4 MSB-D7 (in), 5 D6 (in), 6 D5 (in), 7 D4 (in), 8 D3 (in), 9 D2 (in), 10 D1 (in), 11 LSB-D0 (in), 12 CS (in), 13 WR (in), 14 Vdd (in), 15 V-in (in), 16 Rfb
2 alternate drawings of the same symbol

## AD7118
designator U?
footprint DIP-14
pins: 1 AN-GND (in), 2 MSB-D5 (in), 3 D4 (in), 4 D3 (in), 5 D2 (in), 6 D1 (in), 7 LSB-D0 (in), 8 GND (power) hidden to GND, 11 Vdd (in), 12 V-in (in), 13 Rfb, 14 Iout
2 alternate drawings of the same symbol

## AD7520
designator U?
footprint DIP-16
pins: 1 Iout1, 2 Iout2, 3 GND (power) hidden to GND, 4 MSB-1 (in), 5 BIT-2 (in), 6 BIT-3 (in), 7 BIT-4 (in), 8 BIT-5 (in), 9 BIT-6 (in), 10 BIT-7 (in), 11 BIT-8 (in), 12 BIT-9 (in), 13 LSB-10 (in), 14 Vdd (in), 15 VrefIN (in), 16 Rfb
2 alternate drawings of the same symbol

## AD7521
designator U?
footprint DIP-18
pins: 1 Iout1, 2 Iout2, 3 GND (power) hidden to GND, 4 MSB-1 (in), 5 BIT-2 (in), 6 BIT-3 (in), 7 BIT-4 (in), 8 BIT-5 (in), 9 BIT-6 (in), 10 BIT-7 (in), 11 BIT-8 (in), 12 BIT-9 (in), 13 BIT-10 (in), 14 BIT-11 (in), 15 LSB-12 (in), 16 Vdd (in), 17 VrefIN (in), 18 Rfb
2 alternate drawings of the same symbol

## AD7522
designator U?
footprint DIP-28
pins: 1 +Vdd (in), 2 LDTR, 3 Vref (in), 4 Rfb2, 5 Rfb1, 6 Iout1, 7 Iout2, 8 A-GND (in), 9 SRO (out), 10 msbDB9 (in), 11 DB8 (in), 12 DB7 (in), 13 DB6 (in), 14 DB5 (in), 15 DB4 (in), 16 DB3 (in), 17 DB2 (in), 18 DB1 (in), 19 lsbDB0 (in), 20 SC8 (in), 21 SPC (in), 22 L-DAC (in), 24 LBS (in), 25 HBS (in), 26 SRI (in), 27 VCC (in), 28 GND (power) hidden to GND
2 alternate drawings of the same symbol

## AD7523
designator U?
footprint DIP-16
pins: 1 OUT-1, 2 OUT-2, 3 GND (power) hidden to GND, 4 MSB-1 (in), 5 BIT-2 (in), 6 BIT-3 (in), 7 BIT-4 (in), 8 BIT-5 (in), 9 BIT-6 (in), 10 BIT-7 (in), 11 LBS-8 (in), 14 +Vdd (in), 15 VrefIN (in), 16 Rfb
2 alternate drawings of the same symbol

## AD7524
designator U?
footprint DIP-16
pins: 1 OUT-1, 2 OUT-2, 3 GND (power) hidden to GND, 4 msbDB7 (in), 5 DB6 (in), 6 DB5 (in), 7 DB4 (in), 8 DB3 (in), 9 DB2 (in), 10 DB1 (in), 11 lsbDB0 (in), 12 CS (in), 13 WR (in), 14 +Vdd (in), 15 Vref (in), 16 Rfb
2 alternate drawings of the same symbol

## AD7525
designator U?
footprint DIP-18
pins: 1 OUT, 2 GND (power) hidden to GND, 3 1.0DIG (in), 4 0.1D-8 (in), 5 0.1D-4 (in), 6 0.1D-2 (in), 7 0.1D-1 (in), 8 .01D-8 (in), 9 .01D-4 (in), 10 .01D-2 (in), 11 .01D-1 (in), 12 .001D8 (in), 13 .001D4 (in), 14 .001D2 (in), 15 .001D1 (in), 16 +Vdd (in), 17 Vin (in), 18 Rfb
2 alternate drawings of the same symbol

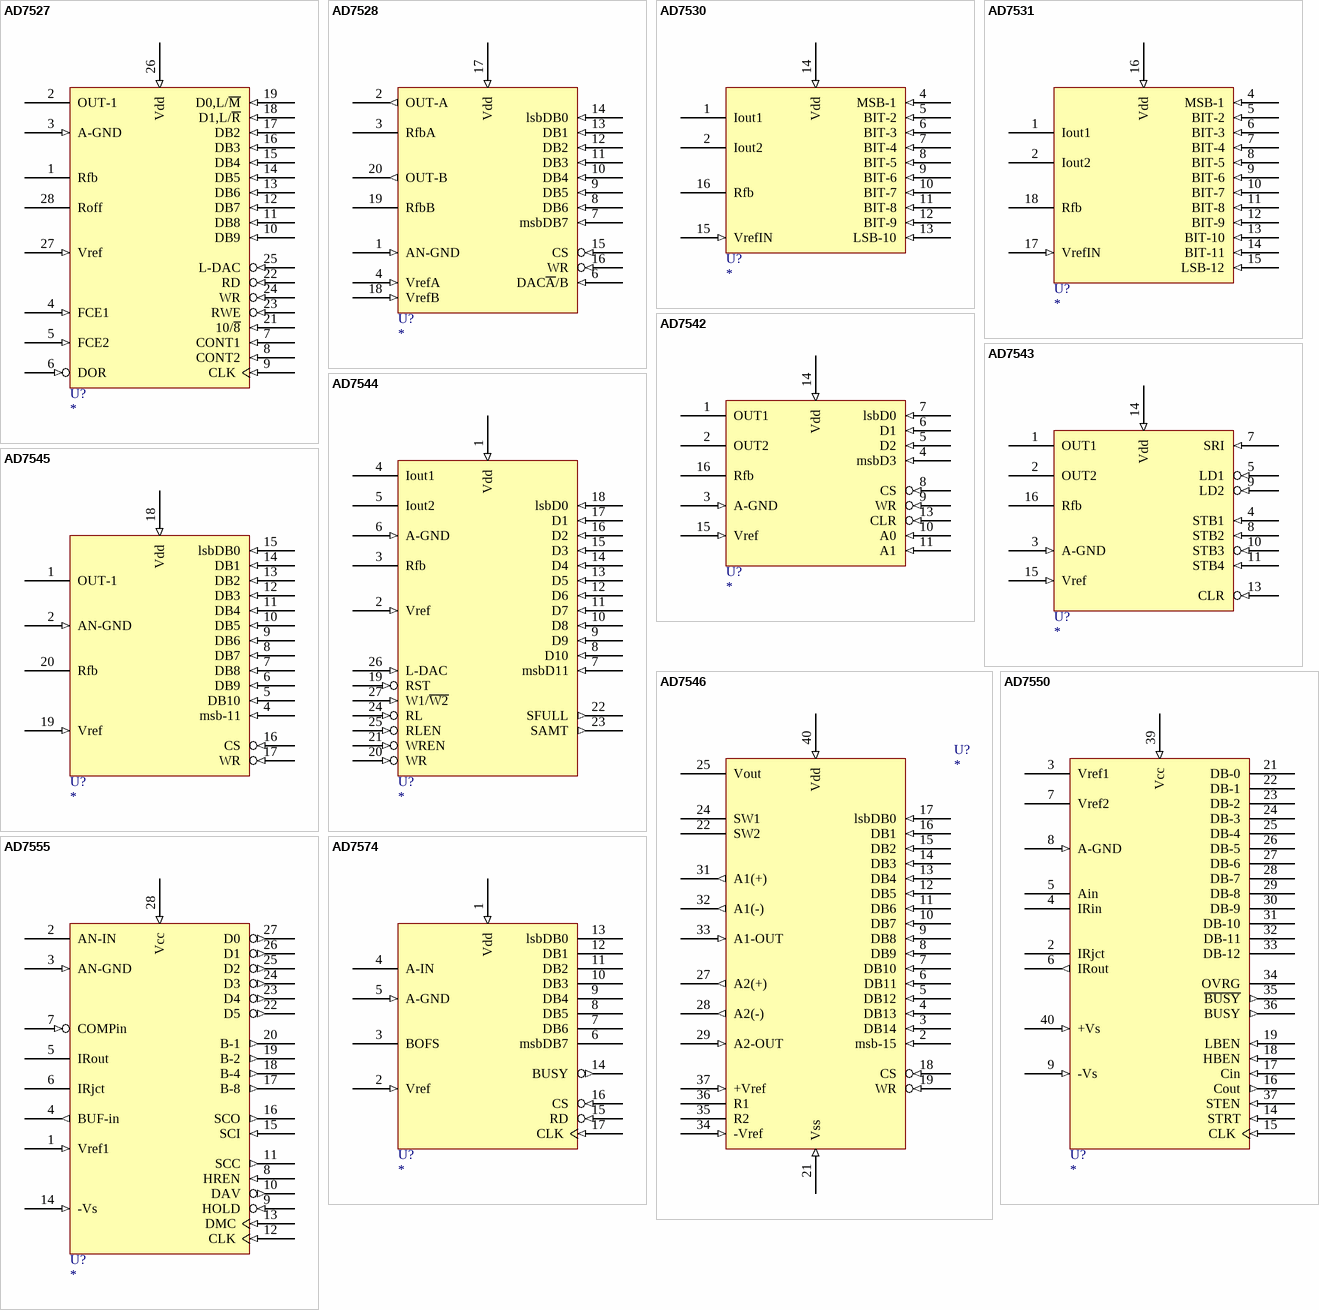
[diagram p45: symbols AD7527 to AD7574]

## AD7527
designator U?
footprint DIP-28
pins: 1 Rfb, 2 OUT-1, 3 A-GND (in), 4 FCE1 (in), 5 FCE2 (in), 6 DOR (in), 7 CONT1 (in), 8 CONT2 (in), 9 CLK (in), 10 DB9 (in), 11 DB8 (in), 12 DB7 (in), 13 DB6 (in), 14 DB5 (in), 15 DB4 (in), 16 DB3 (in), 17 DB2 (in), 18 D1,L/~{R} (in), 19 D0,L/~{M} (in), 20 GND (power) hidden to GND, 21 10/~{8} (in), 22 RD (in), 23 RWE (in), 24 WR (in), 25 L-DAC (in), 26 Vdd (in), 27 Vref (in), 28 Roff
2 alternate drawings of the same symbol

## AD7528
designator U?
footprint DIP20E
pins: 1 AN-GND (in), 2 OUT-A (out), 3 RfbA, 4 VrefA (in), 5 GND (power) hidden to GND, 6 DAC~{A}/B (in), 7 msbDB7 (in), 8 DB6 (in), 9 DB5 (in), 10 DB4 (in), 11 DB3 (in), 12 DB2 (in), 13 DB1 (in), 14 lsbDB0 (in), 15 CS (in), 16 WR (in), 17 Vdd (in), 18 VrefB (in), 19 RfbB, 20 OUT-B (out)
2 alternate drawings of the same symbol

## AD7530
designator U?
footprint DIP-16
pins: 1 Iout1, 2 Iout2, 3 GND (power) hidden to GND, 4 MSB-1 (in), 5 BIT-2 (in), 6 BIT-3 (in), 7 BIT-4 (in), 8 BIT-5 (in), 9 BIT-6 (in), 10 BIT-7 (in), 11 BIT-8 (in), 12 BIT-9 (in), 13 LSB-10 (in), 14 Vdd (in), 15 VrefIN (in), 16 Rfb
2 alternate drawings of the same symbol

## AD7531
designator U?
footprint DIP-18
pins: 1 Iout1, 2 Iout2, 3 GND (power) hidden to GND, 4 MSB-1 (in), 5 BIT-2 (in), 6 BIT-3 (in), 7 BIT-4 (in), 8 BIT-5 (in), 9 BIT-6 (in), 10 BIT-7 (in), 11 BIT-8 (in), 12 BIT-9 (in), 13 BIT-10 (in), 14 BIT-11 (in), 15 LSB-12 (in), 16 Vdd (in), 17 VrefIN (in), 18 Rfb
2 alternate drawings of the same symbol

## AD7542
designator U?
footprint DIP-16
pins: 1 OUT1, 2 OUT2, 3 A-GND (in), 4 msbD3 (in), 5 D2 (in), 6 D1 (in), 7 lsbD0 (in), 8 CS (in), 9 WR (in), 10 A0 (in), 11 A1 (in), 12 GND (power) hidden to GND, 13 CLR (in), 14 Vdd (in), 15 Vref (in), 16 Rfb
2 alternate drawings of the same symbol

## AD7543
designator U?
footprint DIP-16
pins: 1 OUT1, 2 OUT2, 3 A-GND (in), 4 STB1 (in), 5 LD1 (in), 7 SRI (in), 8 STB2 (in), 9 LD2 (in), 10 STB3 (in), 11 STB4 (in), 12 GND (power) hidden to GND, 13 CLR (in), 14 Vdd (in), 15 Vref (in), 16 Rfb
2 alternate drawings of the same symbol

## AD7544
designator U?
footprint DIP-28
pins: 1 Vdd (in), 2 Vref (in), 3 Rfb, 4 Iout1, 5 Iout2, 6 A-GND (in), 7 msbD11 (in), 8 D10 (in), 9 D9 (in), 10 D8 (in), 11 D7 (in), 12 D6 (in), 13 D5 (in), 14 D4 (in), 15 D3 (in), 16 D2 (in), 17 D1 (in), 18 lsbD0 (in), 19 RST (in), 20 WR (in), 21 WREN (in), 22 SFULL (out), 23 SAMT (out), 24 RL (in), 25 RLEN (in), 26 L-DAC (in), 27 W1/~{W2} (in), 28 GND (power) hidden to GND
2 alternate drawings of the same symbol

## AD7545
designator U?
footprint DIP-20
pins: 1 OUT-1, 2 AN-GND (in), 3 GND (power) hidden to GND, 4 msb-11 (in), 5 DB10 (in), 6 DB9 (in), 7 DB8 (in), 8 DB7 (in), 9 DB6 (in), 10 DB5 (in), 11 DB4 (in), 12 DB3 (in), 13 DB2 (in), 14 DB1 (in), 15 lsbDB0 (in), 16 CS (in), 17 WR (in), 18 Vdd (in), 19 Vref (in), 20 Rfb
2 alternate drawings of the same symbol

## AD7546
designator U?
footprint DIP-40
pins: 2 msb-15 (in), 3 DB14 (in), 4 DB13 (in), 5 DB12 (in), 6 DB11 (in), 7 DB10 (in), 8 DB9 (in), 9 DB8 (in), 10 DB7 (in), 11 DB6 (in), 12 DB5 (in), 13 DB4 (in), 14 DB3 (in), 15 DB2 (in), 16 DB1 (in), 17 lsbDB0 (in), 18 CS (in), 19 WR (in), 20 GND (power) hidden to GND, 21 Vss (in), 22 SW2, 24 SW1, 25 Vout, 27 A2(+) (out), 28 A2(-) (out), 29 A2-OUT (in), 31 A1(+) (out), 32 A1(-) (out), 33 A1-OUT (in), 34 -Vref (in), 35 R2, 36 R1, 37 +Vref (in), 40 Vdd (in)
2 alternate drawings of the same symbol

## AD7550
designator U?
footprint DIP-40
pins: 2 IRjct, 3 Vref1, 4 IRin, 5 Ain, 6 IRout (out), 7 Vref2, 8 A-GND (in), 9 -Vs (in), 14 STRT (in), 15 CLK (in), 16 Cout (out), 17 Cin (in), 18 HBEN (in), 19 LBEN (in), 20 GND (power) hidden to GND, 21 DB-0 (hiz), 22 DB-1 (hiz), 23 DB-2 (hiz), 24 DB-3 (hiz), 25 DB-4 (hiz), 26 DB-5 (hiz), 27 DB-6 (hiz), 28 DB-7 (hiz), 29 DB-8 (hiz), 30 DB-9 (hiz), 31 DB-10 (hiz), 32 DB-11 (hiz), 33 DB-12 (hiz), 34 OVRG (hiz), 35 ~{BUSY} (out), 36 BUSY (out), 37 STEN (in), 39 Vcc (in), 40 +Vs (in)
2 alternate drawings of the same symbol

## AD7555
designator U?
footprint DIP-28
pins: 1 Vref1 (in), 2 AN-IN, 3 AN-GND (in), 4 BUF-in (out), 5 IRout, 6 IRjct, 7 COMPin (in), 8 HREN (in), 9 HOLD (in), 10 DAV (out), 11 SCC (out), 12 CLK (in), 13 DMC (in), 14 -Vs (in), 15 SCI (in), 16 SCO (out), 17 B-8 (out), 18 B-4 (out), 19 B-2 (out), 20 B-1 (out), 21 GND (power) hidden to GND, 22 D5 (out), 23 D4 (out), 24 D3 (out), 25 D2 (out), 26 D1 (out), 27 D0 (out), 28 Vcc (in)
2 alternate drawings of the same symbol

## AD7574
designator U?
footprint DIP-18
pins: 1 Vdd (in), 2 Vref (in), 3 BOFS, 4 A-IN, 5 A-GND (in), 6 msbDB7 (hiz), 7 DB6 (hiz), 8 DB5 (hiz), 9 DB4 (hiz), 10 DB3 (hiz), 11 DB2 (hiz), 12 DB1 (hiz), 13 lsbDB0 (hiz), 14 BUSY (out), 15 RD (in), 16 CS (in), 17 CLK (in), 18 GND (power) hidden to GND
2 alternate drawings of the same symbol

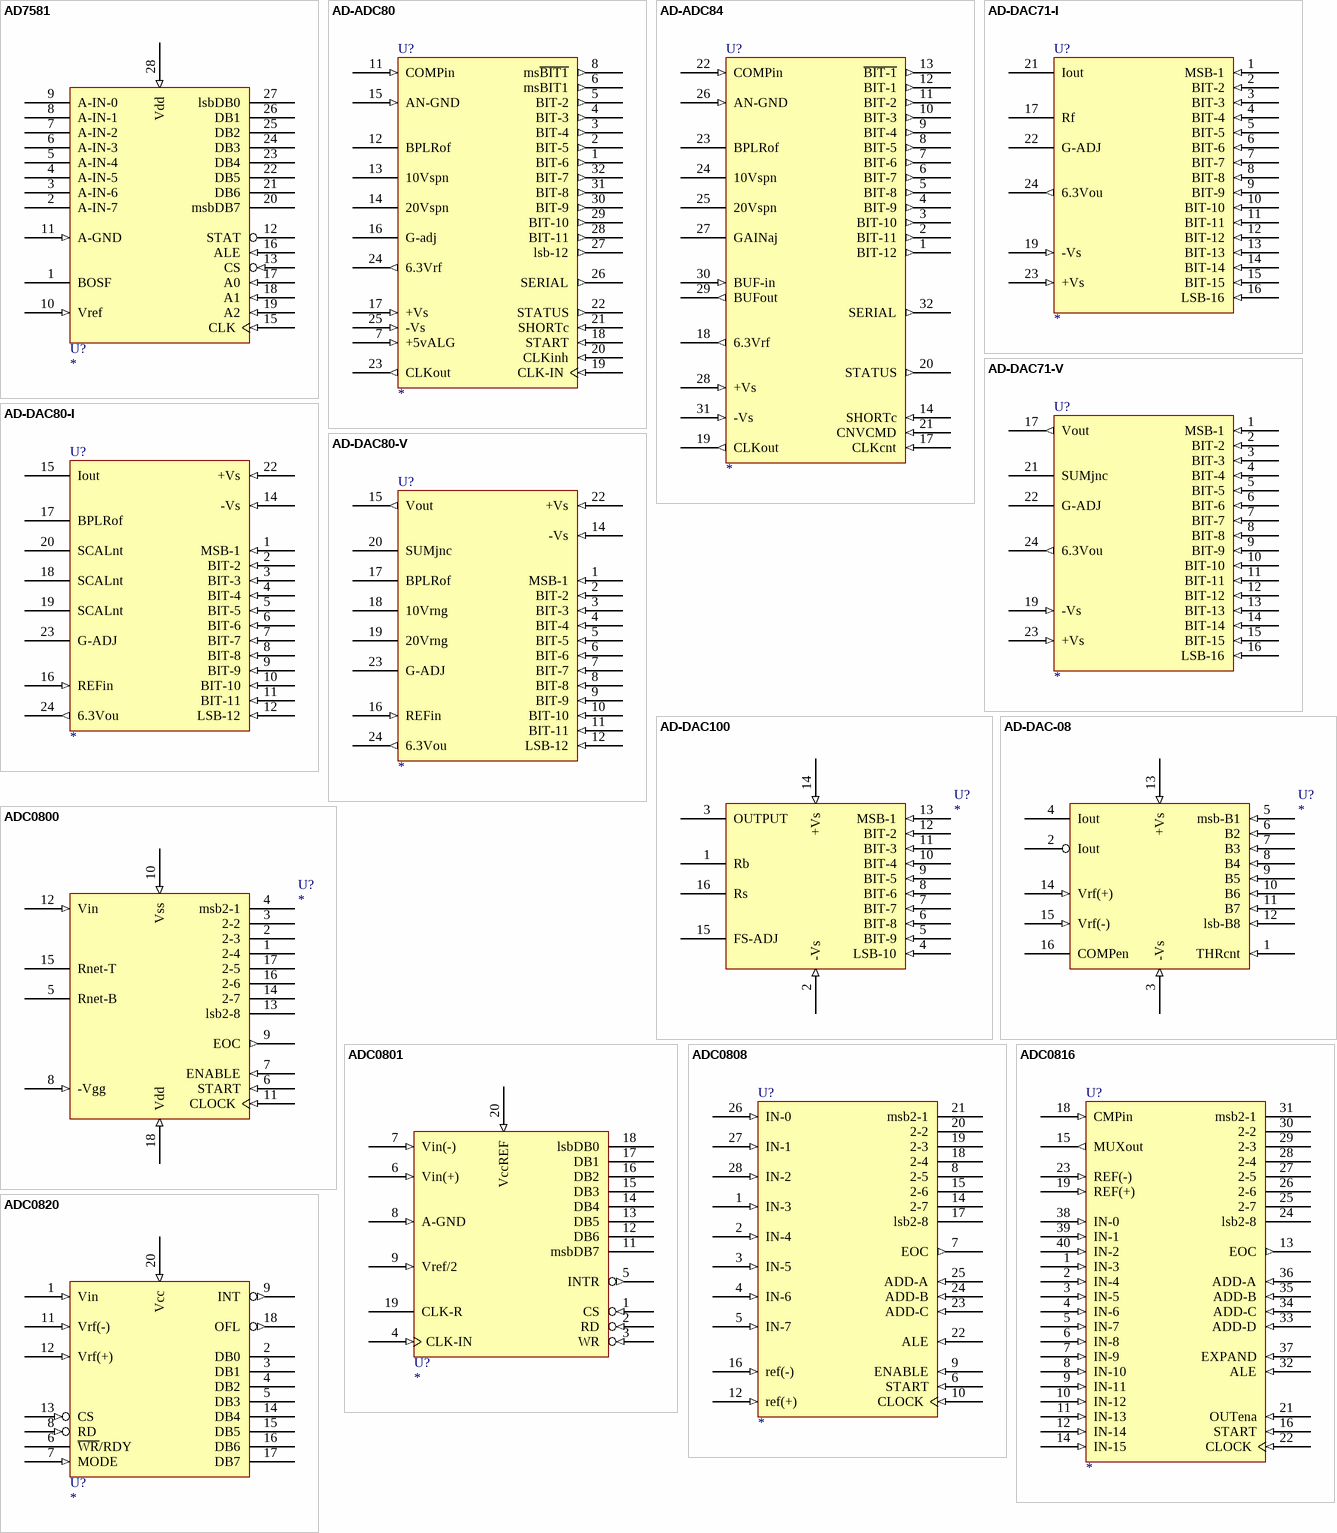
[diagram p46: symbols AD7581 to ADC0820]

## AD7581
designator U?
footprint DIP-18
pins: 1 BOSF, 2 A-IN-7, 3 A-IN-6, 4 A-IN-5, 5 A-IN-4, 6 A-IN-3, 7 A-IN-2, 8 A-IN-1, 9 A-IN-0, 10 Vref (in), 11 A-GND (in), 12 STAT, 13 CS (in), 14 GND (power) hidden to GND, 15 CLK (in), 16 ALE (in), 17 A0 (in), 18 A1 (in), 19 A2 (in), 20 msbDB7 (hiz), 21 DB6 (hiz), 22 DB5 (hiz), 23 DB4 (hiz), 24 DB3 (hiz), 25 DB2 (hiz), 26 DB1 (hiz), 27 lsbDB0 (hiz), 28 Vdd (in)
2 alternate drawings of the same symbol

## AD-ADC80
designator U?
footprint DIP-32
pins: 1 BIT-6 (out), 2 BIT-5 (out), 3 BIT-4 (out), 4 BIT-3 (out), 5 BIT-2 (out), 6 msBIT1 (out), 7 +5vALG (in), 8 ms~{BIT1} (out), 9 VCC (power) hidden to VCC, 10 GND (power) hidden to GND, 11 COMPin (in), 12 BPLRof, 13 10Vspn, 14 20Vspn, 15 AN-GND (in), 16 G-adj, 17 +Vs (in), 18 START (in), 19 CLK-IN (in), 20 CLKinh (in), 21 SHORTc (in), 22 STATUS (out), 23 CLKout (out), 24 6.3Vrf (out), 25 -Vs (in), 26 SERIAL (out), 27 lsb-12 (out), 28 BIT-11 (out), 29 BIT-10 (out), 30 BIT-9 (out), 31 BIT-8 (out), 32 BIT-7 (out)
2 alternate drawings of the same symbol

## AD-ADC84
designator U?
footprint DIP-32
pins: 1 BIT-12 (out), 2 BIT-11 (out), 3 BIT-10 (out), 4 BIT-9 (out), 5 BIT-8 (out), 6 BIT-7 (out), 7 BIT-6 (out), 8 BIT-5 (out), 9 BIT-4 (out), 10 BIT-3 (out), 11 BIT-2 (out), 12 BIT-1 (out), 13 ~{BIT-1} (out), 14 SHORTc (in), 15 GND (power) hidden to GND, 16 VCC (power) hidden to VCC, 17 CLKcnt (in), 18 6.3Vrf (out), 19 CLKout (out), 20 STATUS (out), 21 CNVCMD (in), 22 COMPin (in), 23 BPLRof, 24 10Vspn, 25 20Vspn, 26 AN-GND (in), 27 GAINaj, 28 +Vs (in), 29 BUFout (out), 30 BUF-in (in), 31 -Vs (in), 32 SERIAL (out)
2 alternate drawings of the same symbol

## AD-DAC71-I
designator U?
footprint DIP-24
pins: 1 MSB-1 (in), 2 BIT-2 (in), 3 BIT-3 (in), 4 BIT-4 (in), 5 BIT-5 (in), 6 BIT-6 (in), 7 BIT-7 (in), 8 BIT-8 (in), 9 BIT-9 (in), 10 BIT-10 (in), 11 BIT-11 (in), 12 BIT-12 (in), 13 BIT-13 (in), 14 BIT-14 (in), 15 BIT-15 (in), 16 LSB-16 (in), 17 Rf, 18 VCC (power) hidden to VCC, 19 -Vs (in), 20 GND (power) hidden to GND, 21 Iout, 22 G-ADJ, 23 +Vs (in), 24 6.3Vou (out)
2 alternate drawings of the same symbol

## AD-DAC71-V
designator U?
footprint DIP-24
pins: 1 MSB-1 (in), 2 BIT-2 (in), 3 BIT-3 (in), 4 BIT-4 (in), 5 BIT-5 (in), 6 BIT-6 (in), 7 BIT-7 (in), 8 BIT-8 (in), 9 BIT-9 (in), 10 BIT-10 (in), 11 BIT-11 (in), 12 BIT-12 (in), 13 BIT-13 (in), 14 BIT-14 (in), 15 BIT-15 (in), 16 LSB-16 (in), 17 Vout (out), 18 VCC (power) hidden to VCC, 19 -Vs (in), 20 GND (power) hidden to GND, 21 SUMjnc, 22 G-ADJ, 23 +Vs (in), 24 6.3Vou (out)
2 alternate drawings of the same symbol

## AD-DAC80-I
designator U?
footprint DIP-24
pins: 1 MSB-1 (in), 2 BIT-2 (in), 3 BIT-3 (in), 4 BIT-4 (in), 5 BIT-5 (in), 6 BIT-6 (in), 7 BIT-7 (in), 8 BIT-8 (in), 9 BIT-9 (in), 10 BIT-10 (in), 11 BIT-11 (in), 12 LSB-12 (in), 13 VCC (power) hidden to VCC, 14 -Vs (in), 15 Iout, 16 REFin (in), 17 BPLRof, 18 SCALnt, 19 SCALnt, 20 SCALnt, 21 GND (power) hidden to GND, 22 +Vs (in), 23 G-ADJ, 24 6.3Vou (out)
2 alternate drawings of the same symbol

## AD-DAC80-V
designator U?
footprint DIP-24
pins: 1 MSB-1 (in), 2 BIT-2 (in), 3 BIT-3 (in), 4 BIT-4 (in), 5 BIT-5 (in), 6 BIT-6 (in), 7 BIT-7 (in), 8 BIT-8 (in), 9 BIT-9 (in), 10 BIT-10 (in), 11 BIT-11 (in), 12 LSB-12 (in), 13 VCC (power) hidden to VCC, 14 -Vs (in), 15 Vout (out), 16 REFin (in), 17 BPLRof, 18 10Vrng, 19 20Vrng, 20 SUMjnc, 21 GND (power) hidden to GND, 22 +Vs (in), 23 G-ADJ, 24 6.3Vou (out)
2 alternate drawings of the same symbol

## AD-DAC100
designator U?
footprint DIP-16
pins: 1 Rb, 2 -Vs (in), 3 OUTPUT, 4 LSB-10 (in), 5 BIT-9 (in), 6 BIT-8 (in), 7 BIT-7 (in), 8 BIT-6 (in), 9 BIT-5 (in), 10 BIT-4 (in), 11 BIT-3 (in), 12 BIT-2 (in), 13 MSB-1 (in), 14 +Vs (in), 15 FS-ADJ, 16 Rs
2 alternate drawings of the same symbol

## AD-DAC-08
designator U?
footprint DIP-16
pins: 1 THRcnt (in), 2 Iout, 3 -Vs (in), 4 Iout, 5 msb-B1 (in), 6 B2 (in), 7 B3 (in), 8 B4 (in), 9 B5 (in), 10 B6 (in), 11 B7 (in), 12 lsb-B8 (in), 13 +Vs (in), 14 Vrf(+) (in), 15 Vrf(-) (in), 16 COMPen
2 alternate drawings of the same symbol

## ADC0800
designator U?
footprint DIP-18
pins: 1 2-4 (hiz), 2 2-3 (hiz), 3 2-2 (hiz), 4 msb2-1 (hiz), 5 Rnet-B, 6 START (in), 7 ENABLE (in), 8 -Vgg (in), 9 EOC (out), 10 Vss (in), 11 CLOCK (in), 12 Vin (in), 13 lsb2-8 (hiz), 14 2-7 (hiz), 15 Rnet-T, 16 2-6 (hiz), 17 2-5 (hiz), 18 Vdd (in)
2 alternate drawings of the same symbol

## ADC0801
designator U?
footprint DIP20E
pins: 1 CS (in), 2 RD (in), 3 WR (in), 4 CLK-IN (in), 5 INTR (out), 6 Vin(+) (in), 7 Vin(-) (in), 8 A-GND (in), 9 Vref/2 (in), 10 GND (power) hidden to GND, 11 msbDB7 (hiz), 12 DB6 (hiz), 13 DB5 (hiz), 14 DB4 (hiz), 15 DB3 (hiz), 16 DB2 (hiz), 17 DB1 (hiz), 18 lsbDB0 (hiz), 19 CLK-R, 20 VccREF (in)
2 alternate drawings of the same symbol

## ADC0808
designator U?
footprint DIP28E
pins: 1 IN-3 (in), 2 IN-4 (in), 3 IN-5 (in), 4 IN-6 (in), 5 IN-7 (in), 6 START (in), 7 EOC (out), 8 2-5 (hiz), 9 ENABLE (in), 10 CLOCK (in), 11 VCC (power) hidden to VCC, 12 ref(+) (in), 13 GND (power) hidden to GND, 14 2-7 (hiz), 15 2-6 (hiz), 16 ref(-) (in), 17 lsb2-8 (hiz), 18 2-4 (hiz), 19 2-3 (hiz), 20 2-2 (hiz), 21 msb2-1 (hiz), 22 ALE (in), 23 ADD-C (in), 24 ADD-B (in), 25 ADD-A (in), 26 IN-0 (in), 27 IN-1 (in), 28 IN-2 (in)
2 alternate drawings of the same symbol

## ADC0816
designator U?
footprint DIP-40
pins: 1 IN-3 (in), 2 IN-4 (in), 3 IN-5 (in), 4 IN-6 (in), 5 IN-7 (in), 6 IN-8 (in), 7 IN-9 (in), 8 IN-10 (in), 9 IN-11 (in), 10 IN-12 (in), 11 IN-13 (in), 12 IN-14 (in), 13 EOC (out), 14 IN-15 (in), 15 MUXout (out), 16 START (in), 17 VCC (power) hidden to VCC, 18 CMPin (in), 19 REF(+) (in), 20 GND (power) hidden to GND, 21 OUTena (in), 22 CLOCK (in), 23 REF(-) (in), 24 lsb2-8 (hiz), 25 2-7 (hiz), 26 2-6 (hiz), 27 2-5 (hiz), 28 2-4 (hiz), 29 2-3 (hiz), 30 2-2 (hiz), 31 msb2-1 (hiz), 32 ALE (in), 33 ADD-D (in), 34 ADD-C (in), 35 ADD-B (in), 36 ADD-A (in), 37 EXPAND (in), 38 IN-0 (in), 39 IN-1 (in), 40 IN-2 (in)
2 alternate drawings of the same symbol

## ADC0820
designator U?
footprint DIP-20
pins: 1 Vin (in), 2 DB0 (hiz), 3 DB1 (hiz), 4 DB2 (hiz), 5 DB3 (hiz), 6 ~{WR}/RDY (oc), 7 MODE (in), 8 RD (in), 9 INT (out), 10 GND (power) hidden to GND, 11 Vrf(-) (in), 12 Vrf(+) (in), 13 CS (in), 14 DB4 (hiz), 15 DB5 (hiz), 16 DB6 (hiz), 17 DB7 (hiz), 18 OFL (out), 20 Vcc (in)
2 alternate drawings of the same symbol

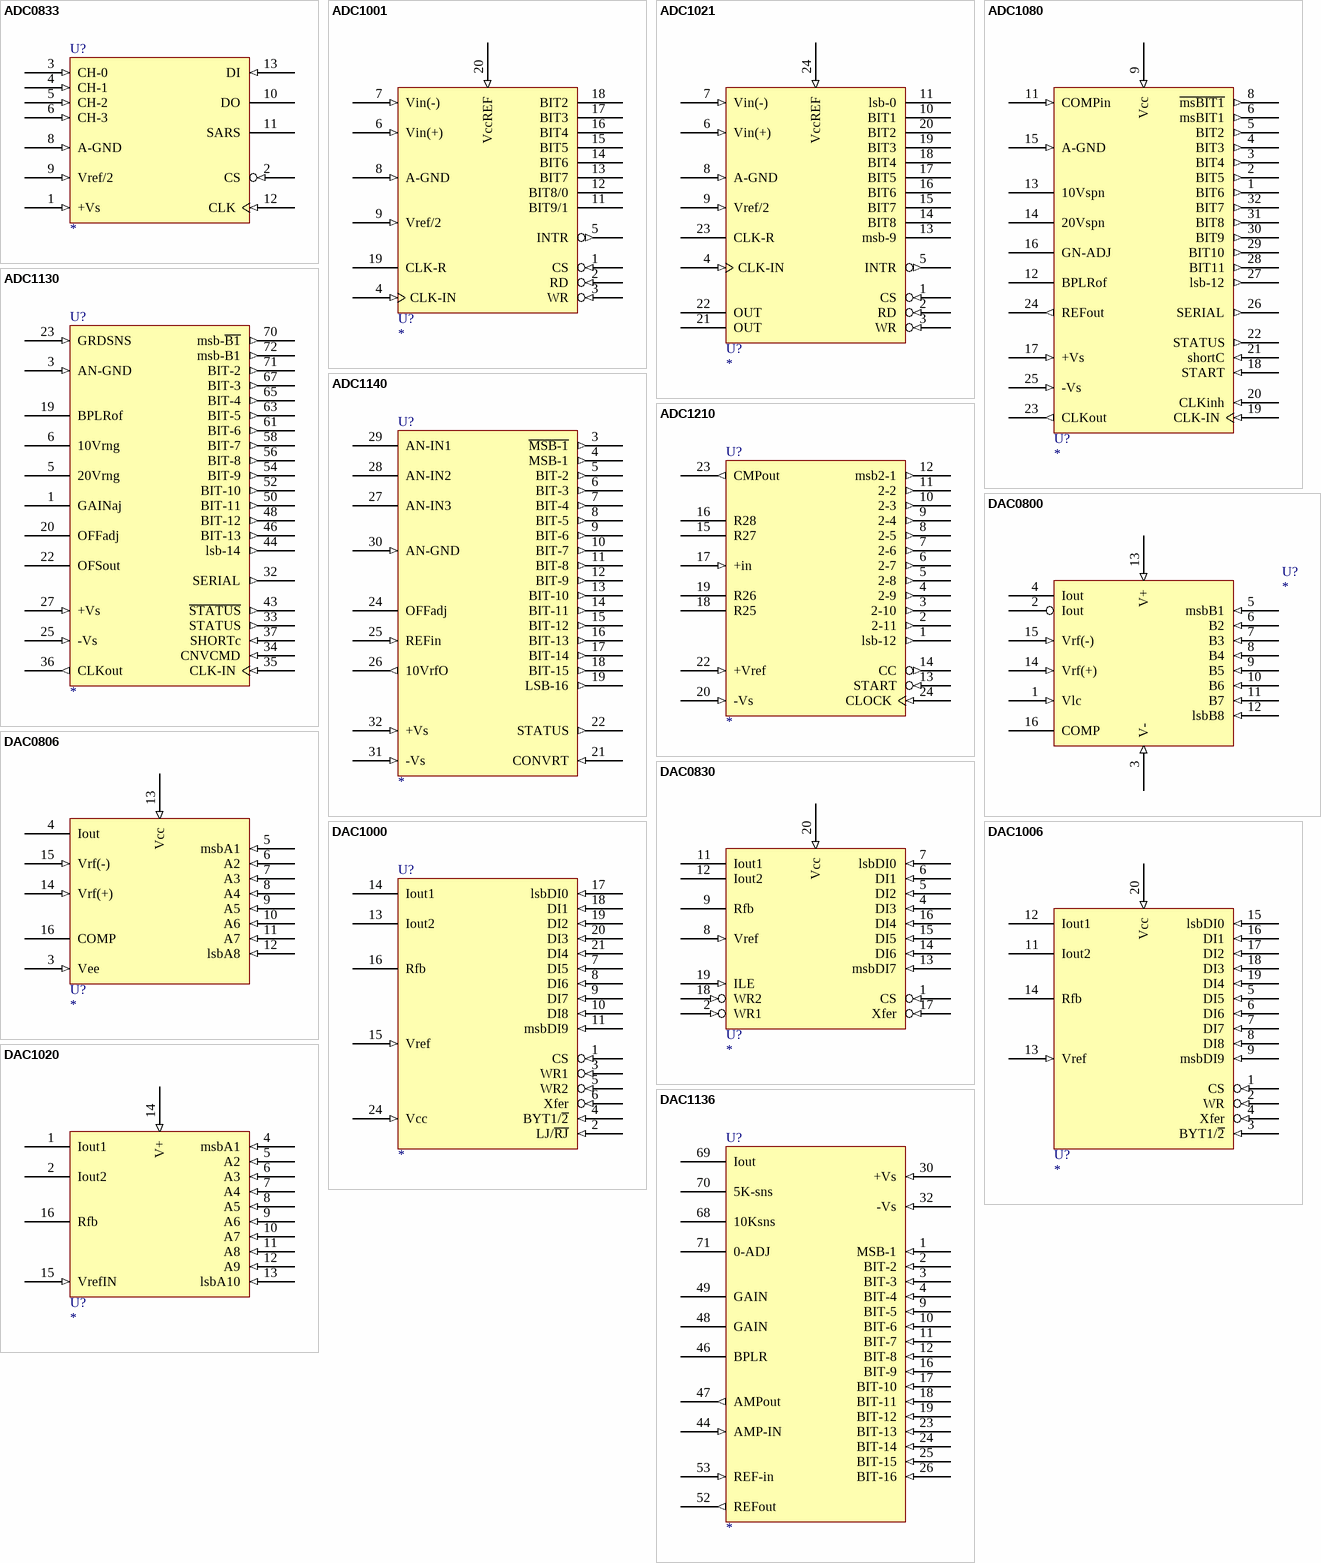
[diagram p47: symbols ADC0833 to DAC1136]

## ADC0833
designator U?
footprint DIP-14
pins: 1 +Vs (in), 2 CS (in), 3 CH-0 (in), 4 CH-1 (in), 5 CH-2 (in), 6 CH-3 (in), 7 GND (power) hidden to GND, 8 A-GND (in), 9 Vref/2 (in), 10 DO (hiz), 11 SARS (hiz), 12 CLK (in), 13 DI (in), 14 VCC (power) hidden to VCC
2 alternate drawings of the same symbol

## ADC1001
designator U?
footprint DIP-20
pins: 1 CS (in), 2 RD (in), 3 WR (in), 4 CLK-IN (in), 5 INTR (out), 6 Vin(+) (in), 7 Vin(-) (in), 8 A-GND (in), 9 Vref/2 (in), 10 GND (power) hidden to GND, 11 BIT9/1 (hiz), 12 BIT8/0 (hiz), 13 BIT7 (hiz), 14 BIT6 (hiz), 15 BIT5 (hiz), 16 BIT4 (hiz), 17 BIT3 (hiz), 18 BIT2 (hiz), 19 CLK-R, 20 VccREF (in)
2 alternate drawings of the same symbol

## ADC1021
designator U?
footprint DIP-24
pins: 1 CS (in), 2 RD (in), 3 WR (in), 4 CLK-IN (in), 5 INTR (out), 6 Vin(+) (in), 7 Vin(-) (in), 8 A-GND (in), 9 Vref/2 (in), 10 BIT1 (hiz), 11 lsb-0 (hiz), 12 GND (power) hidden to GND, 13 msb-9 (hiz), 14 BIT8 (hiz), 15 BIT7 (hiz), 16 BIT6 (hiz), 17 BIT5 (hiz), 18 BIT4 (hiz), 19 BIT3 (hiz), 20 BIT2 (hiz), 21 OUT (hiz), 22 OUT (hiz), 23 CLK-R, 24 VccREF (in)
2 alternate drawings of the same symbol

## ADC1080
designator U?
footprint DIP-32
pins: 1 BIT6 (out), 2 BIT5 (out), 3 BIT4 (out), 4 BIT3 (out), 5 BIT2 (out), 6 msBIT1 (out), 8 ~{msBIT1} (out), 9 Vcc (in), 10 GND (power) hidden to GND, 11 COMPin (in), 12 BPLRof, 13 10Vspn, 14 20Vspn, 15 A-GND (in), 16 GN-ADJ, 17 +Vs (in), 18 START (in), 19 CLK-IN (in), 20 CLKinh (in), 21 shortC (in), 22 STATUS (out), 23 CLKout (out), 24 REFout (out), 25 -Vs (in), 26 SERIAL (out), 27 lsb-12 (out), 28 BIT11 (out), 29 BIT10 (out), 30 BIT9 (out), 31 BIT8 (out), 32 BIT7 (out)
2 alternate drawings of the same symbol

## ADC1130
designator U?
footprint HYB72
pins: 1 GAINaj, 3 AN-GND (in), 5 20Vrng, 6 10Vrng, 19 BPLRof, 20 OFFadj, 22 OFSout, 23 GRDSNS (in), 25 -Vs (in), 27 +Vs (in), 29 VCC (power) hidden to VCC, 30 GND (power) hidden to GND, 32 SERIAL (out), 33 STATUS (out), 34 CNVCMD (in), 35 CLK-IN (in), 36 CLKout (out), 37 SHORTc (in), 43 ~{STATUS} (out), 44 lsb-14 (out), 46 BIT-13 (out), 48 BIT-12 (out), 50 BIT-11 (out), 52 BIT-10 (out), 54 BIT-9 (out), 56 BIT-8 (out), 58 BIT-7 (out), 61 BIT-6 (out), 63 BIT-5 (out), 65 BIT-4 (out), 67 BIT-3 (out), 70 msb-~{B1} (out), 71 BIT-2 (out), 72 msb-B1 (out)
2 alternate drawings of the same symbol

## ADC1140
designator U?
footprint HYB32
pins: 1 VCC (power) hidden to VCC, 2 GND (power) hidden to GND, 3 ~{MSB-1} (out), 4 MSB-1 (out), 5 BIT-2 (out), 6 BIT-3 (out), 7 BIT-4 (out), 8 BIT-5 (out), 9 BIT-6 (out), 10 BIT-7 (out), 11 BIT-8 (out), 12 BIT-9 (out), 13 BIT-10 (out), 14 BIT-11 (out), 15 BIT-12 (out), 16 BIT-13 (out), 17 BIT-14 (out), 18 BIT-15 (out), 19 LSB-16 (out), 21 CONVRT (in), 22 STATUS (out), 24 OFFadj, 25 REFin (in), 26 10VrfO (out), 27 AN-IN3, 28 AN-IN2, 29 AN-IN1, 30 AN-GND (in), 31 -Vs (in), 32 +Vs (in)
2 alternate drawings of the same symbol

## ADC1210
designator U?
footprint DIP-24
pins: 1 lsb-12 (out), 2 2-11 (out), 3 2-10 (out), 4 2-9 (out), 5 2-8 (out), 6 2-7 (out), 7 2-6 (out), 8 2-5 (out), 9 2-4 (out), 10 2-3 (out), 11 2-2 (out), 12 msb2-1 (out), 13 START (in), 14 CC (out), 15 R27, 16 R28, 17 +in (in), 18 R25, 19 R26, 20 -Vs (in), 21 GND (power) hidden to GND, 22 +Vref (in), 23 CMPout (out), 24 CLOCK (in)
2 alternate drawings of the same symbol

## DAC0800
designator U?
footprint DIP-16
pins: 1 Vlc (in), 2 Iout, 3 V- (in), 4 Iout, 5 msbB1 (in), 6 B2 (in), 7 B3 (in), 8 B4 (in), 9 B5 (in), 10 B6 (in), 11 B7 (in), 12 lsbB8 (in), 13 V+ (in), 14 Vrf(+) (in), 15 Vrf(-) (in), 16 COMP
2 alternate drawings of the same symbol

## DAC0806
designator U?
footprint DIP-16
pins: 2 GND (power) hidden to GND, 3 Vee (in), 4 Iout, 5 msbA1 (in), 6 A2 (in), 7 A3 (in), 8 A4 (in), 9 A5 (in), 10 A6 (in), 11 A7 (in), 12 lsbA8 (in), 13 Vcc (in), 14 Vrf(+) (in), 15 Vrf(-) (in), 16 COMP
2 alternate drawings of the same symbol

## DAC0830
designator U?
footprint DIP-20
pins: 1 CS (in), 2 WR1 (in), 3 GND (power) hidden to GND, 4 DI3 (in), 5 DI2 (in), 6 DI1 (in), 7 lsbDI0 (in), 8 Vref (in), 9 Rfb, 10 GND (power) hidden to GND, 11 Iout1, 12 Iout2, 13 msbDI7 (in), 14 DI6 (in), 15 DI5 (in), 16 DI4 (in), 17 Xfer (in), 18 WR2 (in), 19 ILE (in), 20 Vcc (in)
2 alternate drawings of the same symbol

## DAC1000
designator U?
footprint DIP-24
pins: 1 CS (in), 2 LJ/~{RJ} (in), 3 WR1 (in), 4 BYT1/~{2} (in), 5 WR2 (in), 6 Xfer (in), 7 DI5 (in), 8 DI6 (in), 9 DI7 (in), 10 DI8 (in), 11 msbDI9 (in), 12 GND (power) hidden to GND, 13 Iout2, 14 Iout1, 15 Vref (in), 16 Rfb, 17 lsbDI0 (in), 18 DI1 (in), 19 DI2 (in), 20 DI3 (in), 21 DI4 (in), 24 Vcc (in)
2 alternate drawings of the same symbol

## DAC1006
designator U?
footprint DIP-20
pins: 1 CS (in), 2 WR (in), 3 BYT1/~{2} (in), 4 Xfer (in), 5 DI5 (in), 6 DI6 (in), 7 DI7 (in), 8 DI8 (in), 9 msbDI9 (in), 10 GND (power) hidden to GND, 11 Iout2, 12 Iout1, 13 Vref (in), 14 Rfb, 15 lsbDI0 (in), 16 DI1 (in), 17 DI2 (in), 18 DI3 (in), 19 DI4 (in), 20 Vcc (in)
2 alternate drawings of the same symbol

## DAC1020
designator U?
footprint DIP-16
pins: 1 Iout1, 2 Iout2, 3 GND (power) hidden to GND, 4 msbA1 (in), 5 A2 (in), 6 A3 (in), 7 A4 (in), 8 A5 (in), 9 A6 (in), 10 A7 (in), 11 A8 (in), 12 A9 (in), 13 lsbA10 (in), 14 V+ (in), 15 VrefIN (in), 16 Rfb
2 alternate drawings of the same symbol

## DAC1136
designator U?
footprint CARD71
pins: 1 MSB-1 (in), 2 BIT-2 (in), 3 BIT-3 (in), 4 BIT-4 (in), 9 BIT-5 (in), 10 BIT-6 (in), 11 BIT-7 (in), 12 BIT-8 (in), 16 BIT-9 (in), 17 BIT-10 (in), 18 BIT-11 (in), 19 BIT-12 (in), 23 BIT-13 (in), 24 BIT-14 (in), 25 BIT-15 (in), 26 BIT-16 (in), 28 VCC (power) hidden to VCC, 30 +Vs (in), 32 -Vs (in), 34 GND (power) hidden to GND, 44 AMP-IN (in), 46 BPLR, 47 AMPout (out), 48 GAIN, 49 GAIN, 52 REFout (out), 53 REF-in (in), 68 10Ksns, 69 Iout, 70 5K-sns, 71 0-ADJ
2 alternate drawings of the same symbol

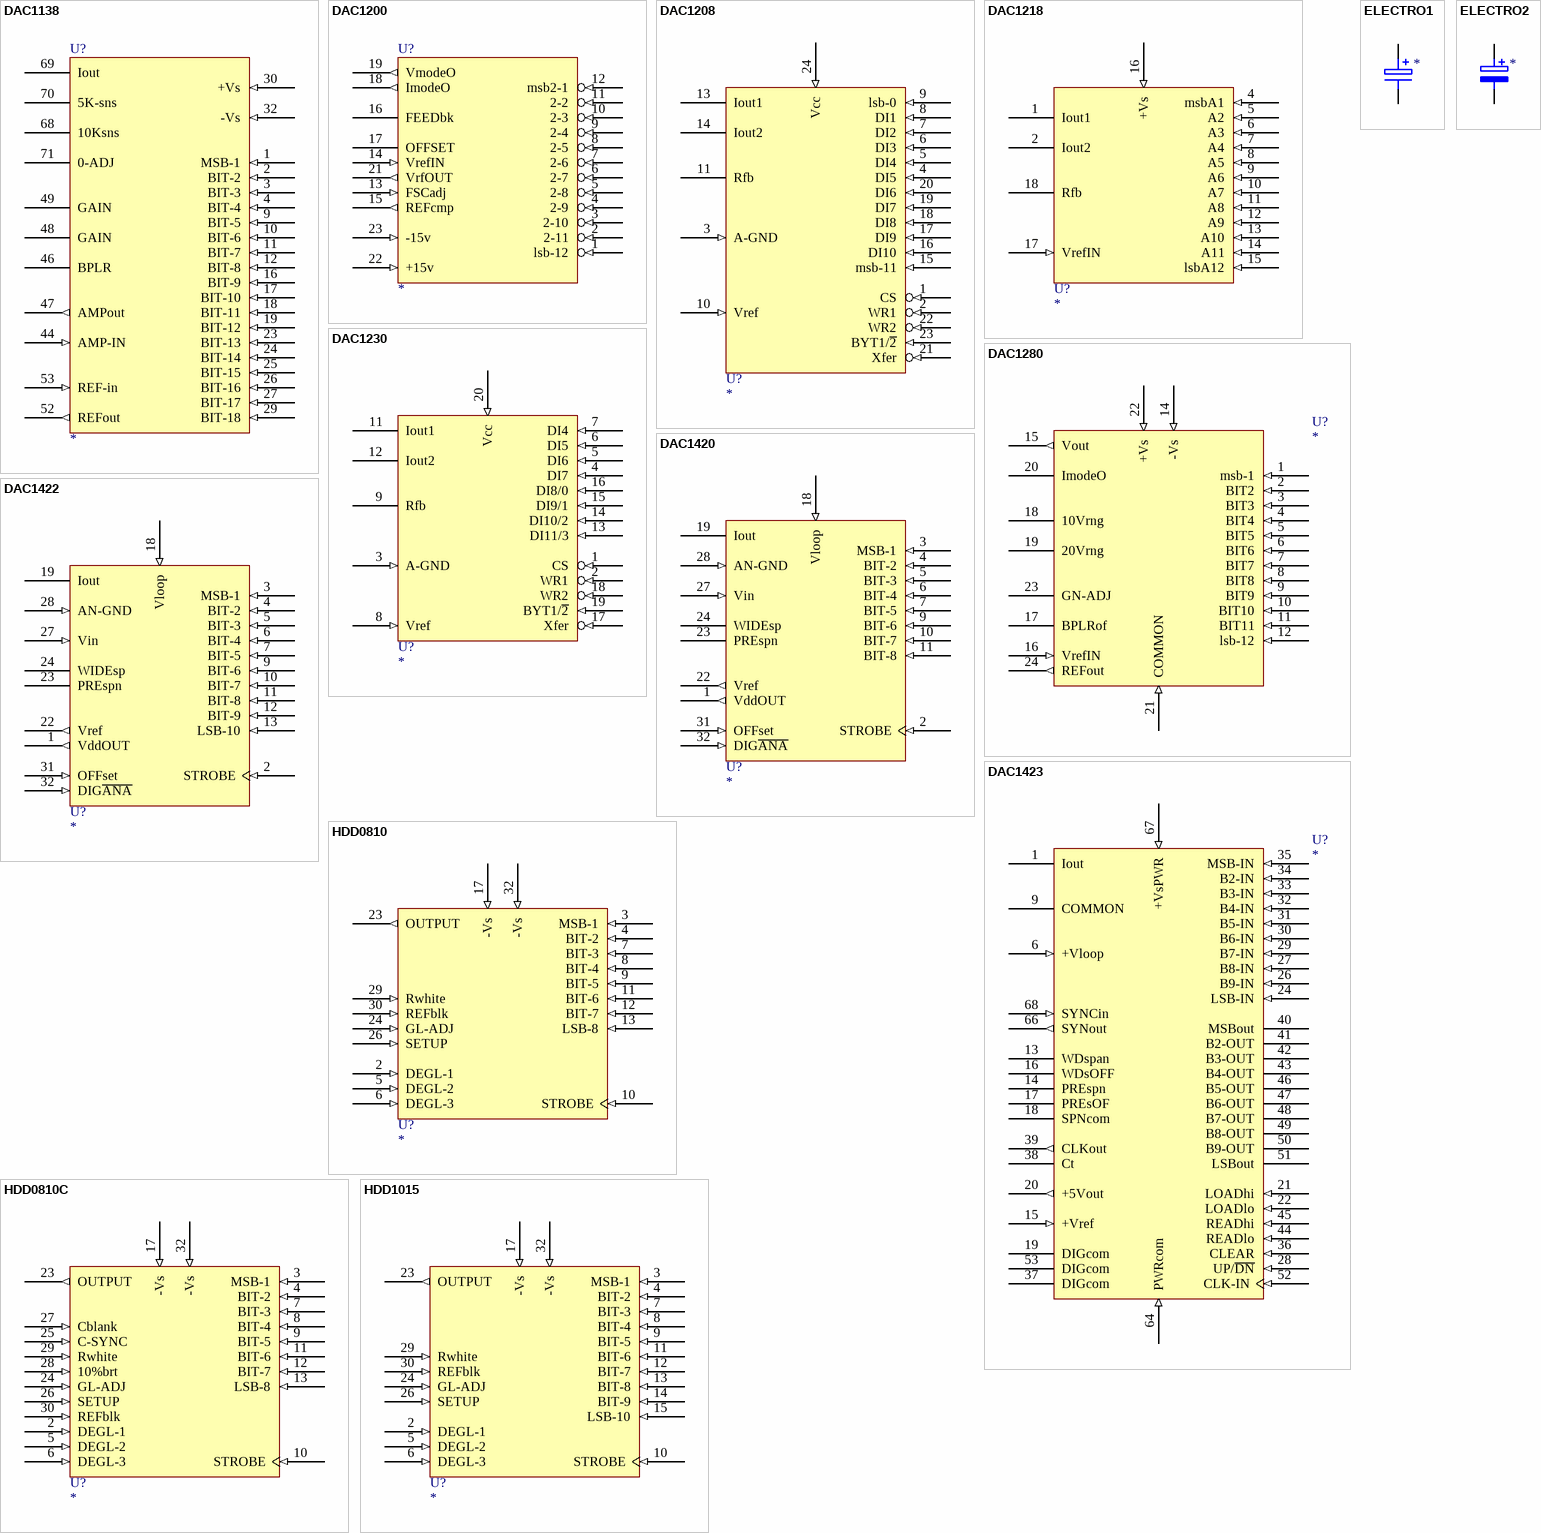
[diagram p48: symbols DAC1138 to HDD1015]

## DAC1138
designator U?
footprint CARD71
pins: 1 MSB-1 (in), 2 BIT-2 (in), 3 BIT-3 (in), 4 BIT-4 (in), 9 BIT-5 (in), 10 BIT-6 (in), 11 BIT-7 (in), 12 BIT-8 (in), 16 BIT-9 (in), 17 BIT-10 (in), 18 BIT-11 (in), 19 BIT-12 (in), 23 BIT-13 (in), 24 BIT-14 (in), 25 BIT-15 (in), 26 BIT-16 (in), 27 BIT-17 (in), 28 VCC (power) hidden to VCC, 29 BIT-18 (in), 30 +Vs (in), 32 -Vs (in), 34 GND (power) hidden to GND, 44 AMP-IN (in), 46 BPLR, 47 AMPout (out), 48 GAIN, 49 GAIN, 52 REFout (out), 53 REF-in (in), 68 10Ksns, 69 Iout, 70 5K-sns, 71 0-ADJ
2 alternate drawings of the same symbol

## DAC1200
designator U?
footprint DIP-24
pins: 1 lsb-12 (in), 2 2-11 (in), 3 2-10 (in), 4 2-9 (in), 5 2-8 (in), 6 2-7 (in), 7 2-6 (in), 8 2-5 (in), 9 2-4 (in), 10 2-3 (in), 11 2-2 (in), 12 msb2-1 (in), 13 FSCadj (in), 14 VrefIN (in), 15 REFcmp (out), 16 FEEDbk, 17 OFFSET, 18 ImodeO (out), 19 VmodeO (out), 20 VCC (power) hidden to VCC, 21 VrfOUT (out), 22 +15v (in), 23 -15v (in), 24 GND (power) hidden to GND
2 alternate drawings of the same symbol

## DAC1208
designator U?
footprint DIP-24
pins: 1 CS (in), 2 WR1 (in), 3 A-GND (in), 4 DI5 (in), 5 DI4 (in), 6 DI3 (in), 7 DI2 (in), 8 DI1 (in), 9 lsb-0 (in), 10 Vref (in), 11 Rfb, 12 GND (power) hidden to GND, 13 Iout1, 14 Iout2, 15 msb-11 (in), 16 DI10 (in), 17 DI9 (in), 18 DI8 (in), 19 DI7 (in), 20 DI6 (in), 21 Xfer (in), 22 WR2 (in), 23 BYT1/~{2} (in), 24 Vcc (in)
2 alternate drawings of the same symbol

## DAC1218
designator U?
footprint DIP-18
pins: 1 Iout1, 2 Iout2, 3 GND (power) hidden to GND, 4 msbA1 (in), 5 A2 (in), 6 A3 (in), 7 A4 (in), 8 A5 (in), 9 A6 (in), 10 A7 (in), 11 A8 (in), 12 A9 (in), 13 A10 (in), 14 A11 (in), 15 lsbA12 (in), 16 +Vs (in), 17 VrefIN (in), 18 Rfb
2 alternate drawings of the same symbol

## DAC1230
designator U?
footprint DIP-20
pins: 1 CS (in), 2 WR1 (in), 3 A-GND (in), 4 DI7 (in), 5 DI6 (in), 6 DI5 (in), 7 DI4 (in), 8 Vref (in), 9 Rfb, 10 GND (power) hidden to GND, 11 Iout1, 12 Iout2, 13 DI11/3 (in), 14 DI10/2 (in), 15 DI9/1 (in), 16 DI8/0 (in), 17 Xfer (in), 18 WR2 (in), 19 BYT1/~{2} (in), 20 Vcc (in)
2 alternate drawings of the same symbol

## DAC1280
designator U?
footprint DIP-24
pins: 1 msb-1 (in), 2 BIT2 (in), 3 BIT3 (in), 4 BIT4 (in), 5 BIT5 (in), 6 BIT6 (in), 7 BIT7 (in), 8 BIT8 (in), 9 BIT9 (in), 10 BIT10 (in), 11 BIT11 (in), 12 lsb-12 (in), 14 -Vs (in), 15 Vout (out), 16 VrefIN (in), 17 BPLRof, 18 10Vrng, 19 20Vrng, 20 ImodeO, 21 COMMON (in), 22 +Vs (in), 23 GN-ADJ, 24 REFout (out)
2 alternate drawings of the same symbol

## DAC1420
designator U?
footprint HYB32
pins: 1 VddOUT (out), 2 STROBE (in), 3 MSB-1 (in), 4 BIT-2 (in), 5 BIT-3 (in), 6 BIT-4 (in), 7 BIT-5 (in), 9 BIT-6 (in), 10 BIT-7 (in), 11 BIT-8 (in), 16 GND (power) hidden to GND, 18 Vloop (in), 19 Iout, 22 Vref (out), 23 PREspn, 24 WIDEsp, 27 Vin (in), 28 AN-GND (in), 31 OFFset (in), 32 DIG~{ANA} (in)
2 alternate drawings of the same symbol

## DAC1422
designator U?
footprint HYB32
pins: 1 VddOUT (out), 2 STROBE (in), 3 MSB-1 (in), 4 BIT-2 (in), 5 BIT-3 (in), 6 BIT-4 (in), 7 BIT-5 (in), 9 BIT-6 (in), 10 BIT-7 (in), 11 BIT-8 (in), 12 BIT-9 (in), 13 LSB-10 (in), 16 GND (power) hidden to GND, 18 Vloop (in), 19 Iout, 22 Vref (out), 23 PREspn, 24 WIDEsp, 27 Vin (in), 28 AN-GND (in), 31 OFFset (in), 32 DIG~{ANA} (in)
2 alternate drawings of the same symbol

## DAC1423
designator U?
footprint HYB72
pins: 1 Iout, 6 +Vloop (in), 9 COMMON, 13 WDspan, 14 PREspn, 15 +Vref (in), 16 WDsOFF, 17 PREsOF, 18 SPNcom, 19 DIGcom, 20 +5Vout (out), 21 LOADhi (in), 22 LOADlo (in), 24 LSB-IN (in), 26 B9-IN (in), 27 B8-IN (in), 28 UP/~{DN} (in), 29 B7-IN (in), 30 B6-IN (in), 31 B5-IN (in), 32 B4-IN (in), 33 B3-IN (in), 34 B2-IN (in), 35 MSB-IN (in), 36 CLEAR (in), 37 DIGcom, 38 Ct, 39 CLKout (out), 40 MSBout (hiz), 41 B2-OUT (hiz), 42 B3-OUT (hiz), 43 B4-OUT (hiz), 44 READlo (in), 45 READhi (in), 46 B5-OUT (hiz), 47 B6-OUT (hiz), 48 B7-OUT (hiz), 49 B8-OUT (hiz), 50 B9-OUT (hiz), 51 LSBout (hiz), 52 CLK-IN (in), 53 DIGcom, 64 PWRcom (in), 66 SYNout (out), 67 +VsPWR (in), 68 SYNCin (in)
2 alternate drawings of the same symbol

## ELECTRO1
designator ?
pins: 1, 2
2 alternate drawings of the same symbol

## ELECTRO2
designator ?
pins: 1, 2
2 alternate drawings of the same symbol

## HDD0810
designator U?
footprint DIP-32
pins: 1 GND (power) hidden to GND, 2 DEGL-1 (in), 3 MSB-1 (in), 4 BIT-2 (in), 5 DEGL-2 (in), 6 DEGL-3 (in), 7 BIT-3 (in), 8 BIT-4 (in), 9 BIT-5 (in), 10 STROBE (in), 11 BIT-6 (in), 12 BIT-7 (in), 13 LSB-8 (in), 16 GND (power) hidden to GND, 17 -Vs (in), 18 GND (power) hidden to GND, 19 GND (power) hidden to GND, 20 GND (power) hidden to GND, 21 GND (power) hidden to GND, 22 GND (power) hidden to GND, 23 OUTPUT (out), 24 GL-ADJ (in), 26 SETUP (in), 29 Rwhite (in), 30 REFblk (in), 31 GND (power) hidden to GND, 32 -Vs (in)
2 alternate drawings of the same symbol

## HDD0810C
designator U?
footprint DIP-32
pins: 1 GND (power) hidden to GND, 2 DEGL-1 (in), 3 MSB-1 (in), 4 BIT-2 (in), 5 DEGL-2 (in), 6 DEGL-3 (in), 7 BIT-3 (in), 8 BIT-4 (in), 9 BIT-5 (in), 10 STROBE (in), 11 BIT-6 (in), 12 BIT-7 (in), 13 LSB-8 (in), 16 GND (power) hidden to GND, 17 -Vs (in), 18 GND (power) hidden to GND, 19 GND (power) hidden to GND, 20 GND (power) hidden to GND, 21 GND (power) hidden to GND, 22 GND (power) hidden to GND, 23 OUTPUT (out), 24 GL-ADJ (in), 25 C-SYNC (in), 26 SETUP (in), 27 Cblank (in), 28 10%brt (in), 29 Rwhite (in), 30 REFblk (in), 31 GND (power) hidden to GND, 32 -Vs (in)
2 alternate drawings of the same symbol

## HDD1015
designator U?
footprint DIP-32
pins: 1 GND (power) hidden to GND, 2 DEGL-1 (in), 3 MSB-1 (in), 4 BIT-2 (in), 5 DEGL-2 (in), 6 DEGL-3 (in), 7 BIT-3 (in), 8 BIT-4 (in), 9 BIT-5 (in), 10 STROBE (in), 11 BIT-6 (in), 12 BIT-7 (in), 13 BIT-8 (in), 14 BIT-9 (in), 15 LSB-10 (in), 16 GND (power) hidden to GND, 17 -Vs (in), 18 GND (power) hidden to GND, 19 GND (power) hidden to GND, 20 GND (power) hidden to GND, 21 GND (power) hidden to GND, 22 GND (power) hidden to GND, 23 OUTPUT (out), 24 GL-ADJ (in), 26 SETUP (in), 29 Rwhite (in), 30 REFblk (in), 31 GND (power) hidden to GND, 32 -Vs (in)
2 alternate drawings of the same symbol

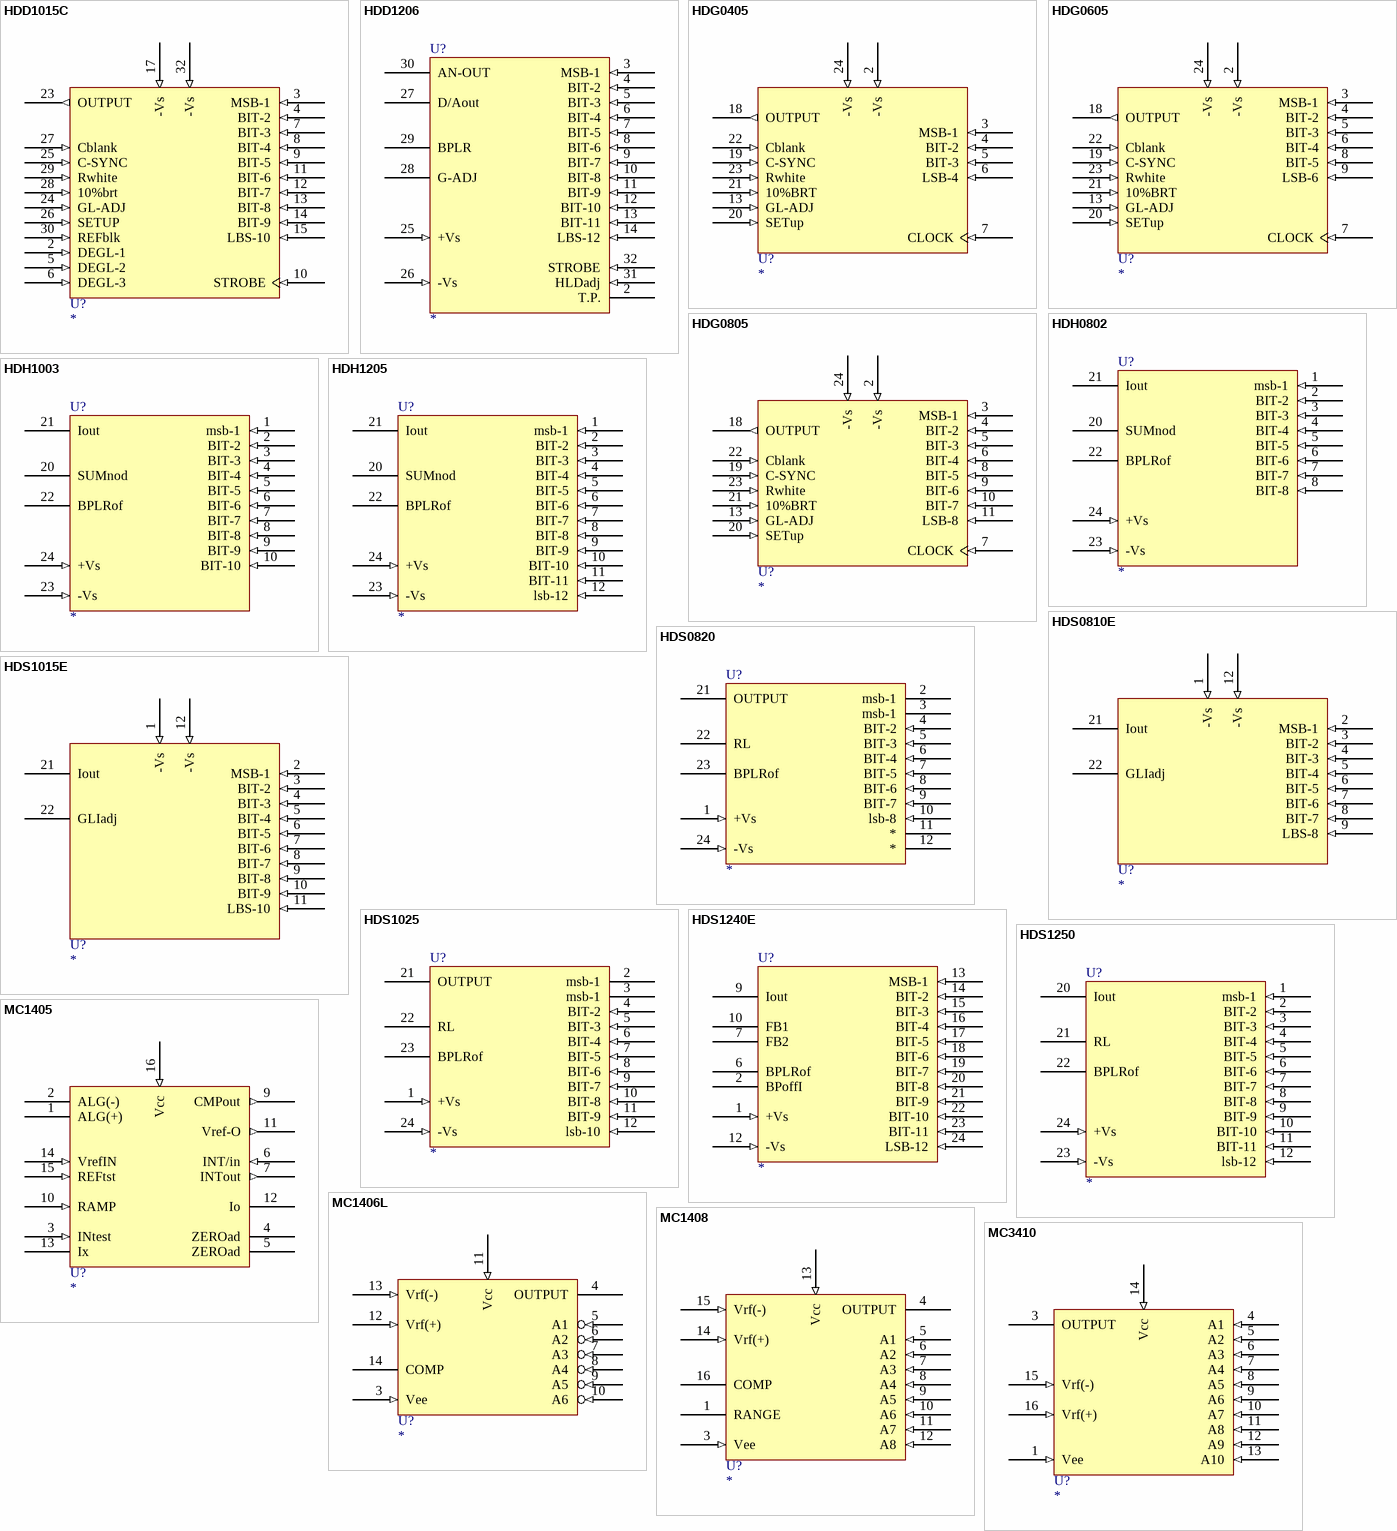
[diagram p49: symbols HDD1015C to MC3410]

## HDD1015C
designator U?
footprint DIP-32
pins: 1 GND (power) hidden to GND, 2 DEGL-1 (in), 3 MSB-1 (in), 4 BIT-2 (in), 5 DEGL-2 (in), 6 DEGL-3 (in), 7 BIT-3 (in), 8 BIT-4 (in), 9 BIT-5 (in), 10 STROBE (in), 11 BIT-6 (in), 12 BIT-7 (in), 13 BIT-8 (in), 14 BIT-9 (in), 15 LBS-10 (in), 16 GND (power) hidden to GND, 17 -Vs (in), 18 GND (power) hidden to GND, 19 GND (power) hidden to GND, 20 GND (power) hidden to GND, 21 GND (power) hidden to GND, 22 GND (power) hidden to GND, 23 OUTPUT (out), 24 GL-ADJ (in), 25 C-SYNC (in), 26 SETUP (in), 27 Cblank (in), 28 10%brt (in), 29 Rwhite (in), 30 REFblk (in), 31 GND (power) hidden to GND, 32 -Vs (in)
2 alternate drawings of the same symbol

## HDD1206
designator U?
footprint DIP-32
pins: 1 GND (power) hidden to GND, 2 T.P., 3 MSB-1 (in), 4 BIT-2 (in), 5 BIT-3 (in), 6 BIT-4 (in), 7 BIT-5 (in), 8 BIT-6 (in), 9 BIT-7 (in), 10 BIT-8 (in), 11 BIT-9 (in), 12 BIT-10 (in), 13 BIT-11 (in), 14 LBS-12 (in), 15 VCC (power) hidden to VCC, 16 GND (power) hidden to GND, 17 GND (power) hidden to GND, 18 GND (power) hidden to GND, 19 GND (power) hidden to GND, 20 GND (power) hidden to GND, 21 GND (power) hidden to GND, 22 GND (power) hidden to GND, 23 GND (power) hidden to GND, 24 GND (power) hidden to GND, 25 +Vs (in), 26 -Vs (in), 27 D/Aout, 28 G-ADJ, 29 BPLR, 30 AN-OUT, 31 HLDadj (in), 32 STROBE (in)
2 alternate drawings of the same symbol

## HDG0405
designator U?
footprint HY24
pins: 1 GND (power) hidden to GND, 2 -Vs (in), 3 MSB-1 (in), 4 BIT-2 (in), 5 BIT-3 (in), 6 LSB-4 (in), 7 CLOCK (in), 12 GND (power) hidden to GND, 13 GL-ADJ (in), 14 GND (power) hidden to GND, 15 GND (power) hidden to GND, 16 GND (power) hidden to GND, 17 GND (power) hidden to GND, 18 OUTPUT (out), 19 C-SYNC (in), 20 SETup (in), 21 10%BRT (in), 22 Cblank (in), 23 Rwhite (in), 24 -Vs (in)
2 alternate drawings of the same symbol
